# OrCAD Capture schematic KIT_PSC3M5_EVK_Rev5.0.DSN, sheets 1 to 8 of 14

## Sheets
1 13. ACCESORIES: title: PSOC CONTROL C3M5 EVALUATION KIT; rev: 5.0; note: 630-60703-01
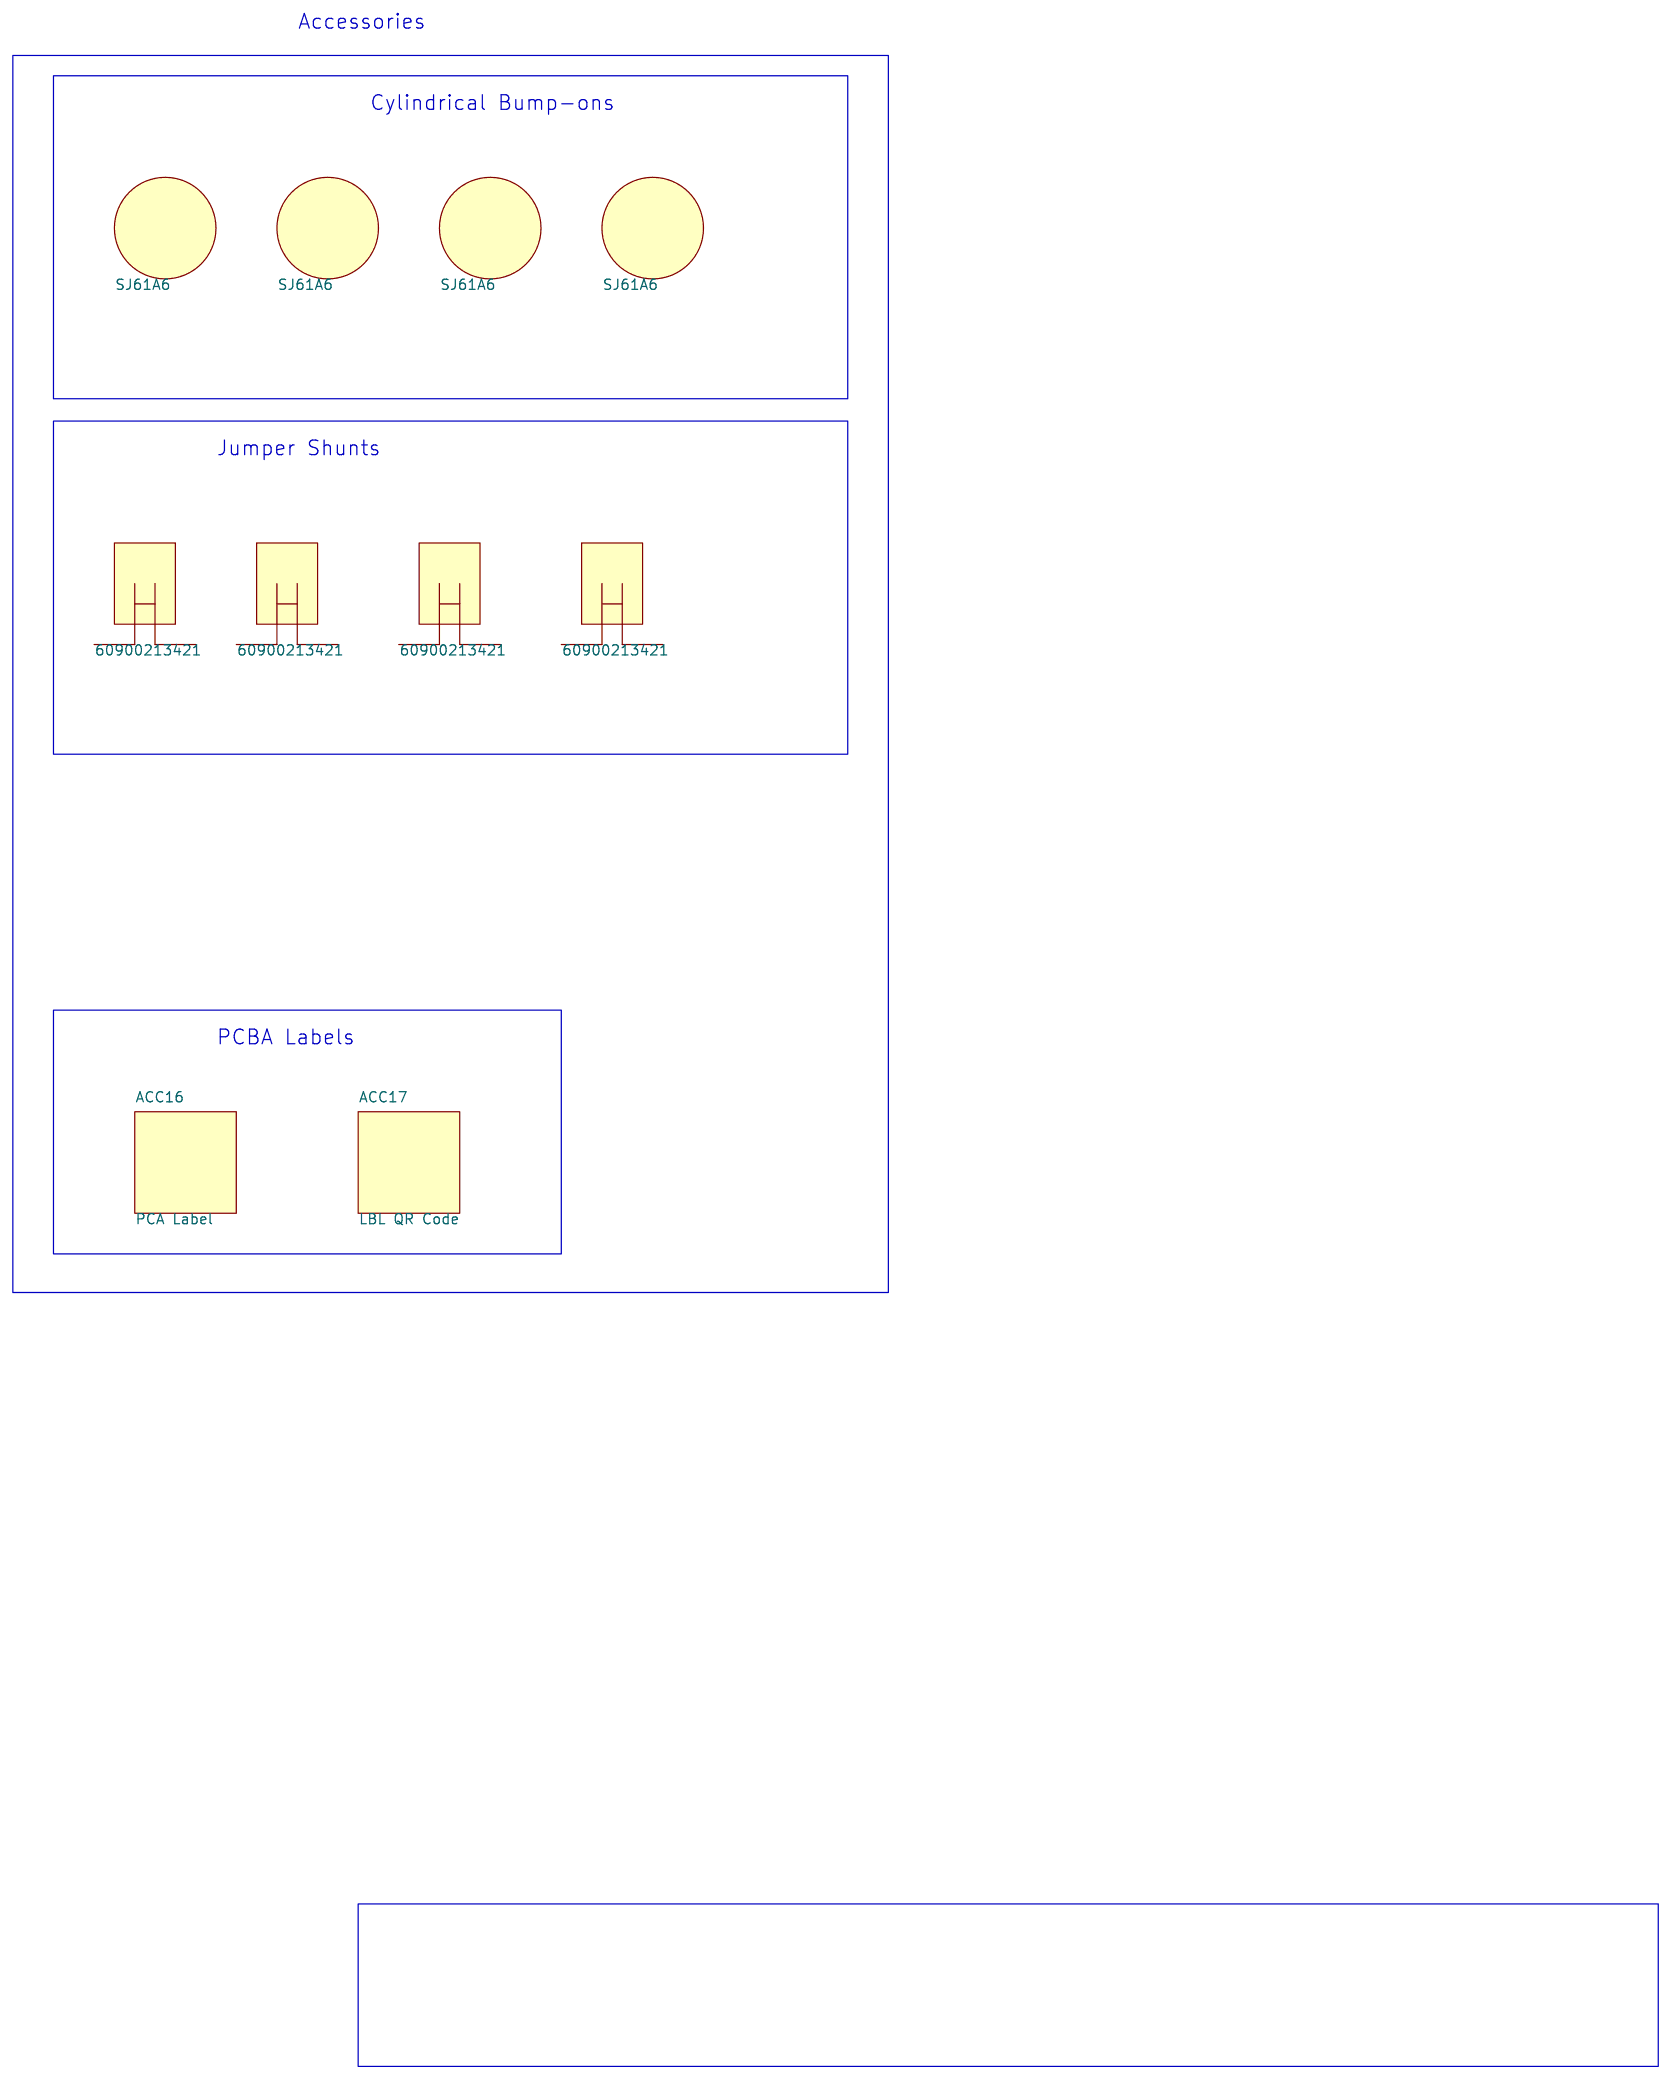
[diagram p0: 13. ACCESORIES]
2 01. TITLE PAGE
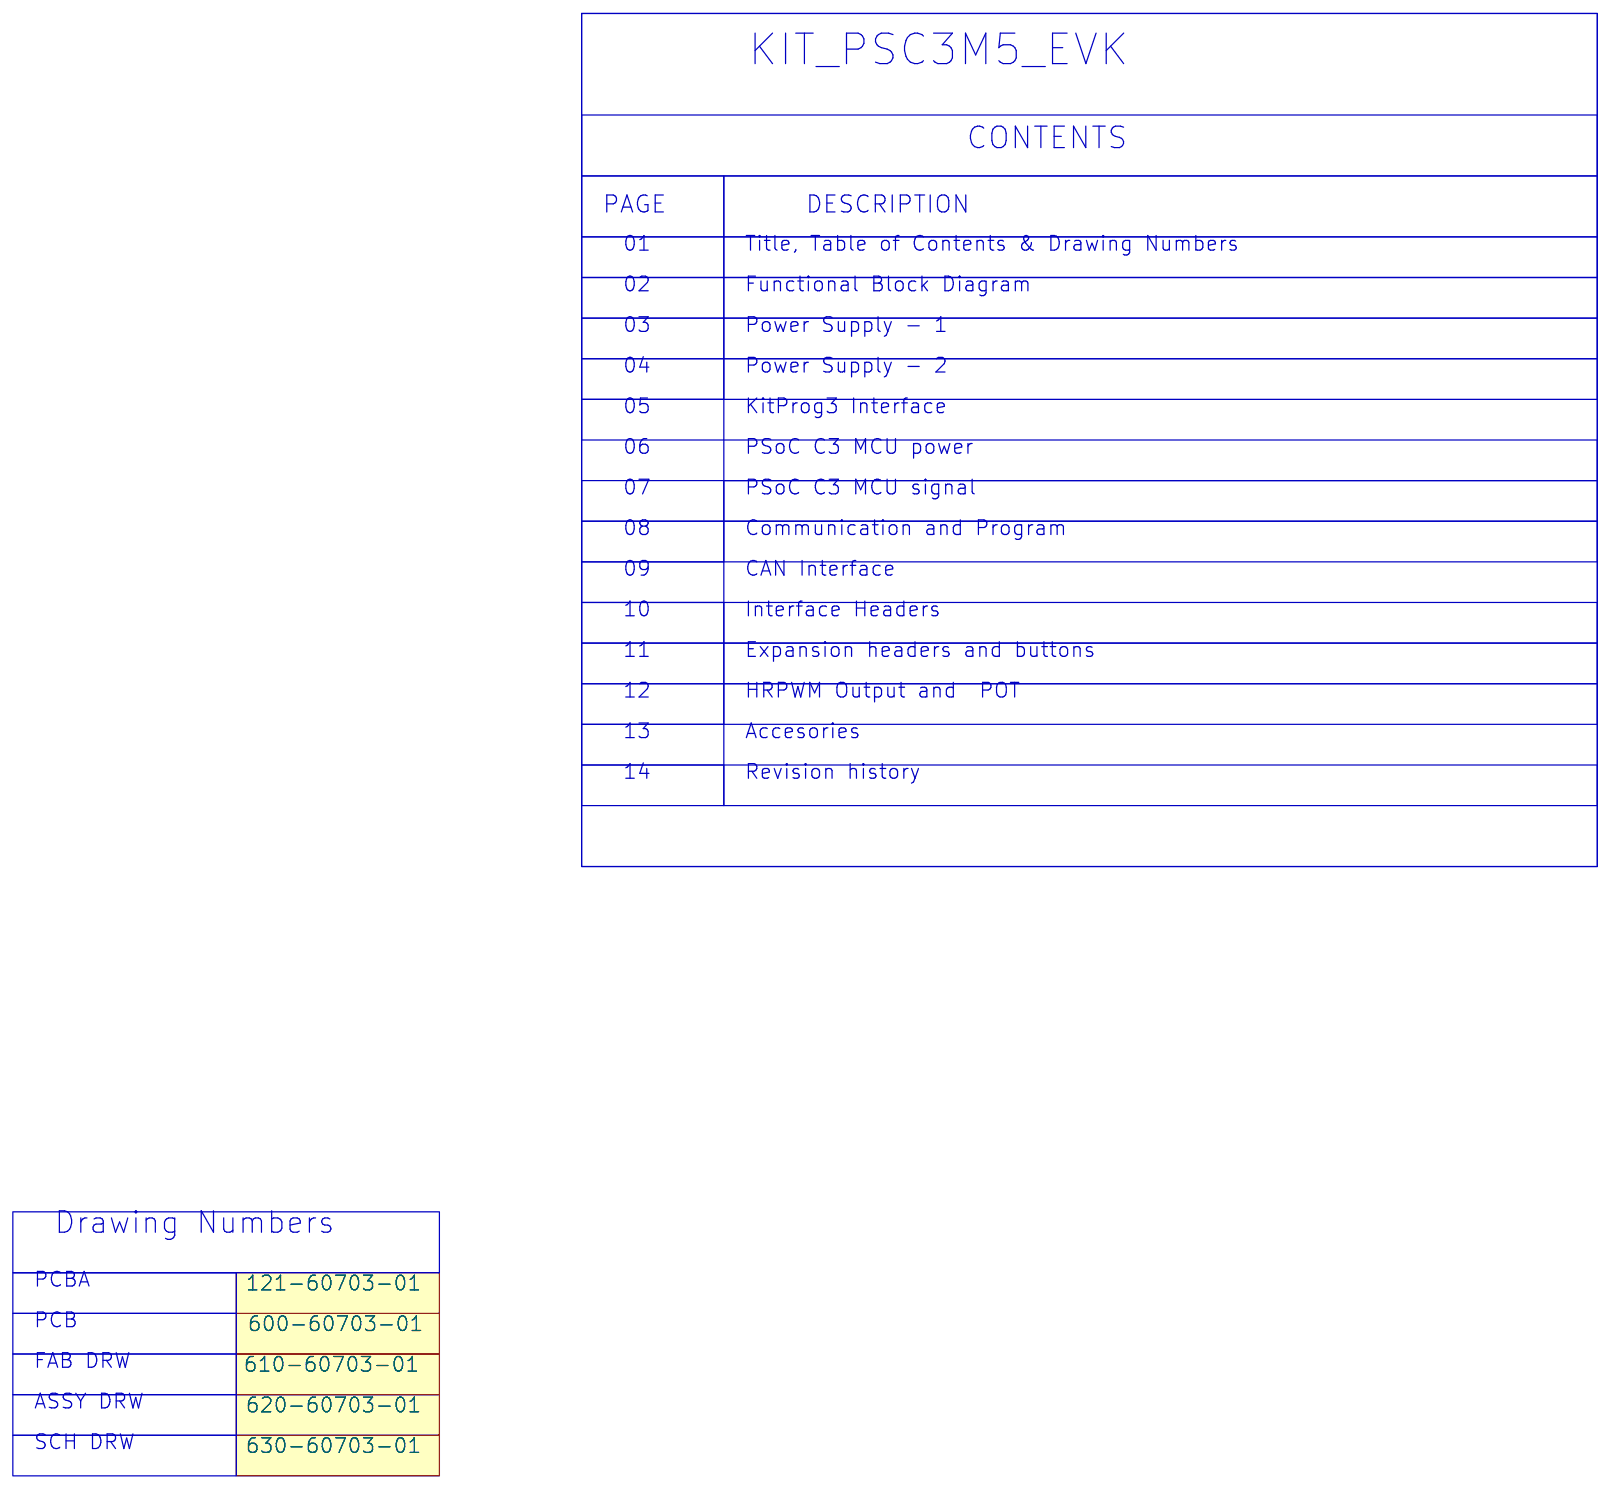
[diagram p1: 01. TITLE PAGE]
3 02. BLOCK DIAGRAM
4 03. POWER SUPPLY-1: size A4
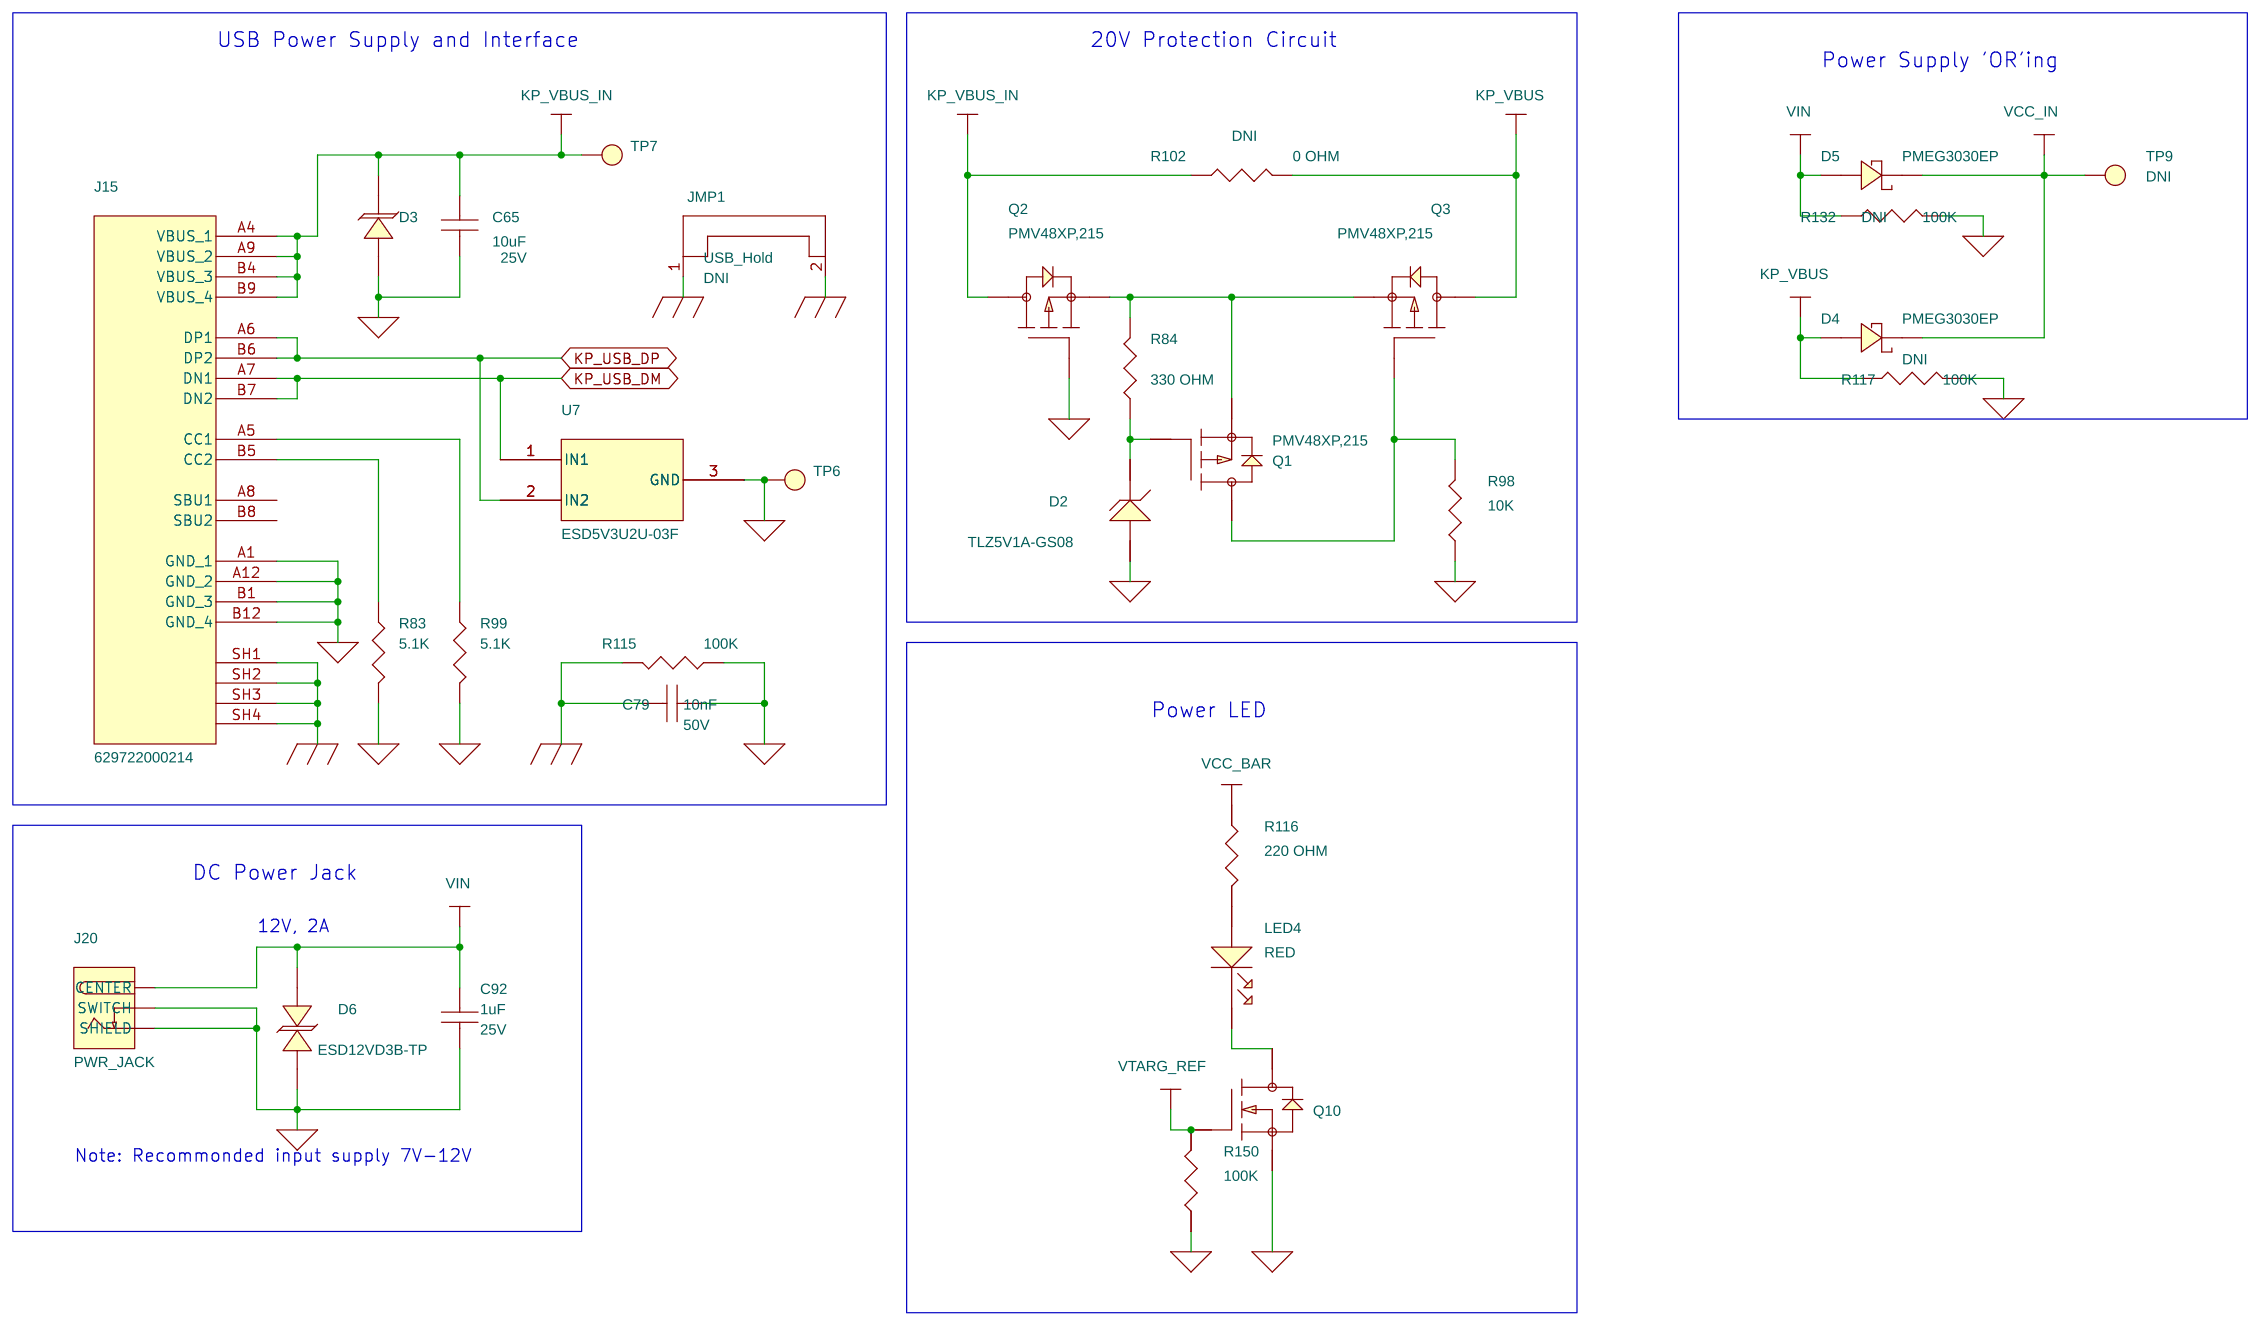
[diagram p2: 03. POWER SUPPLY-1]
5 04. POWER SUPPLY-2: size A4
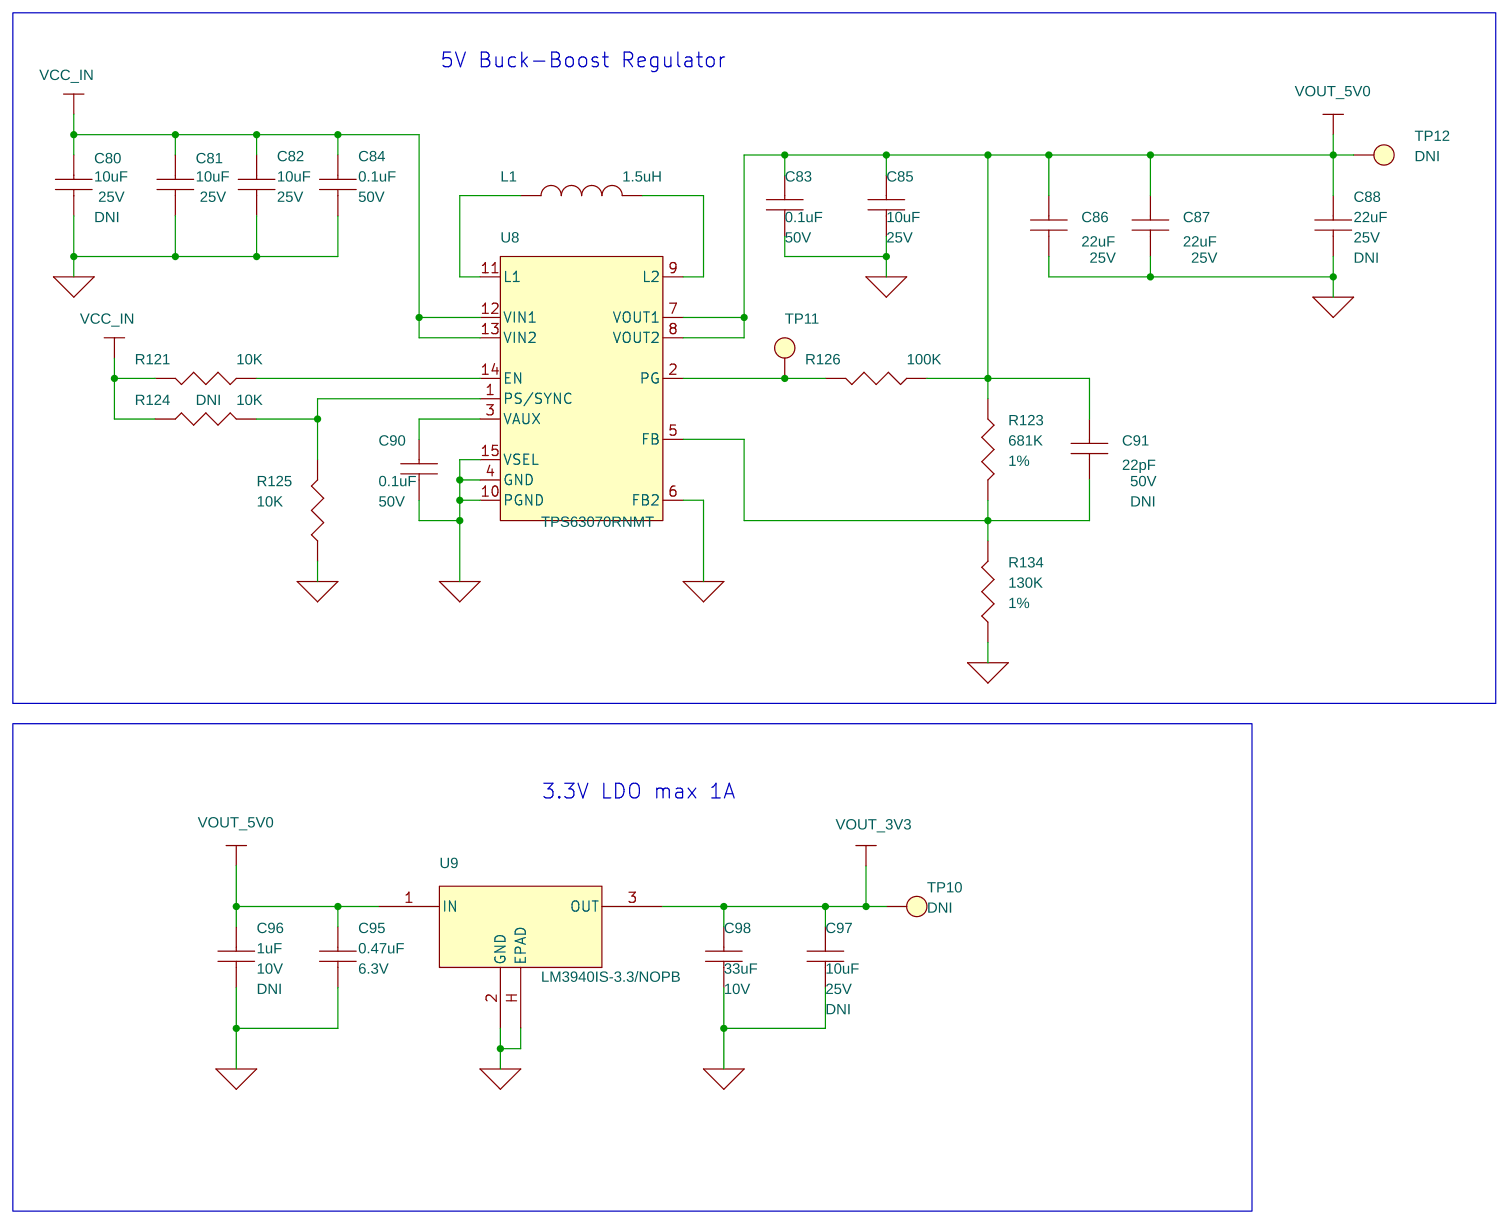
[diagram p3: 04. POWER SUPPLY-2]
6 05. KITPROG INTERFACE: size A4
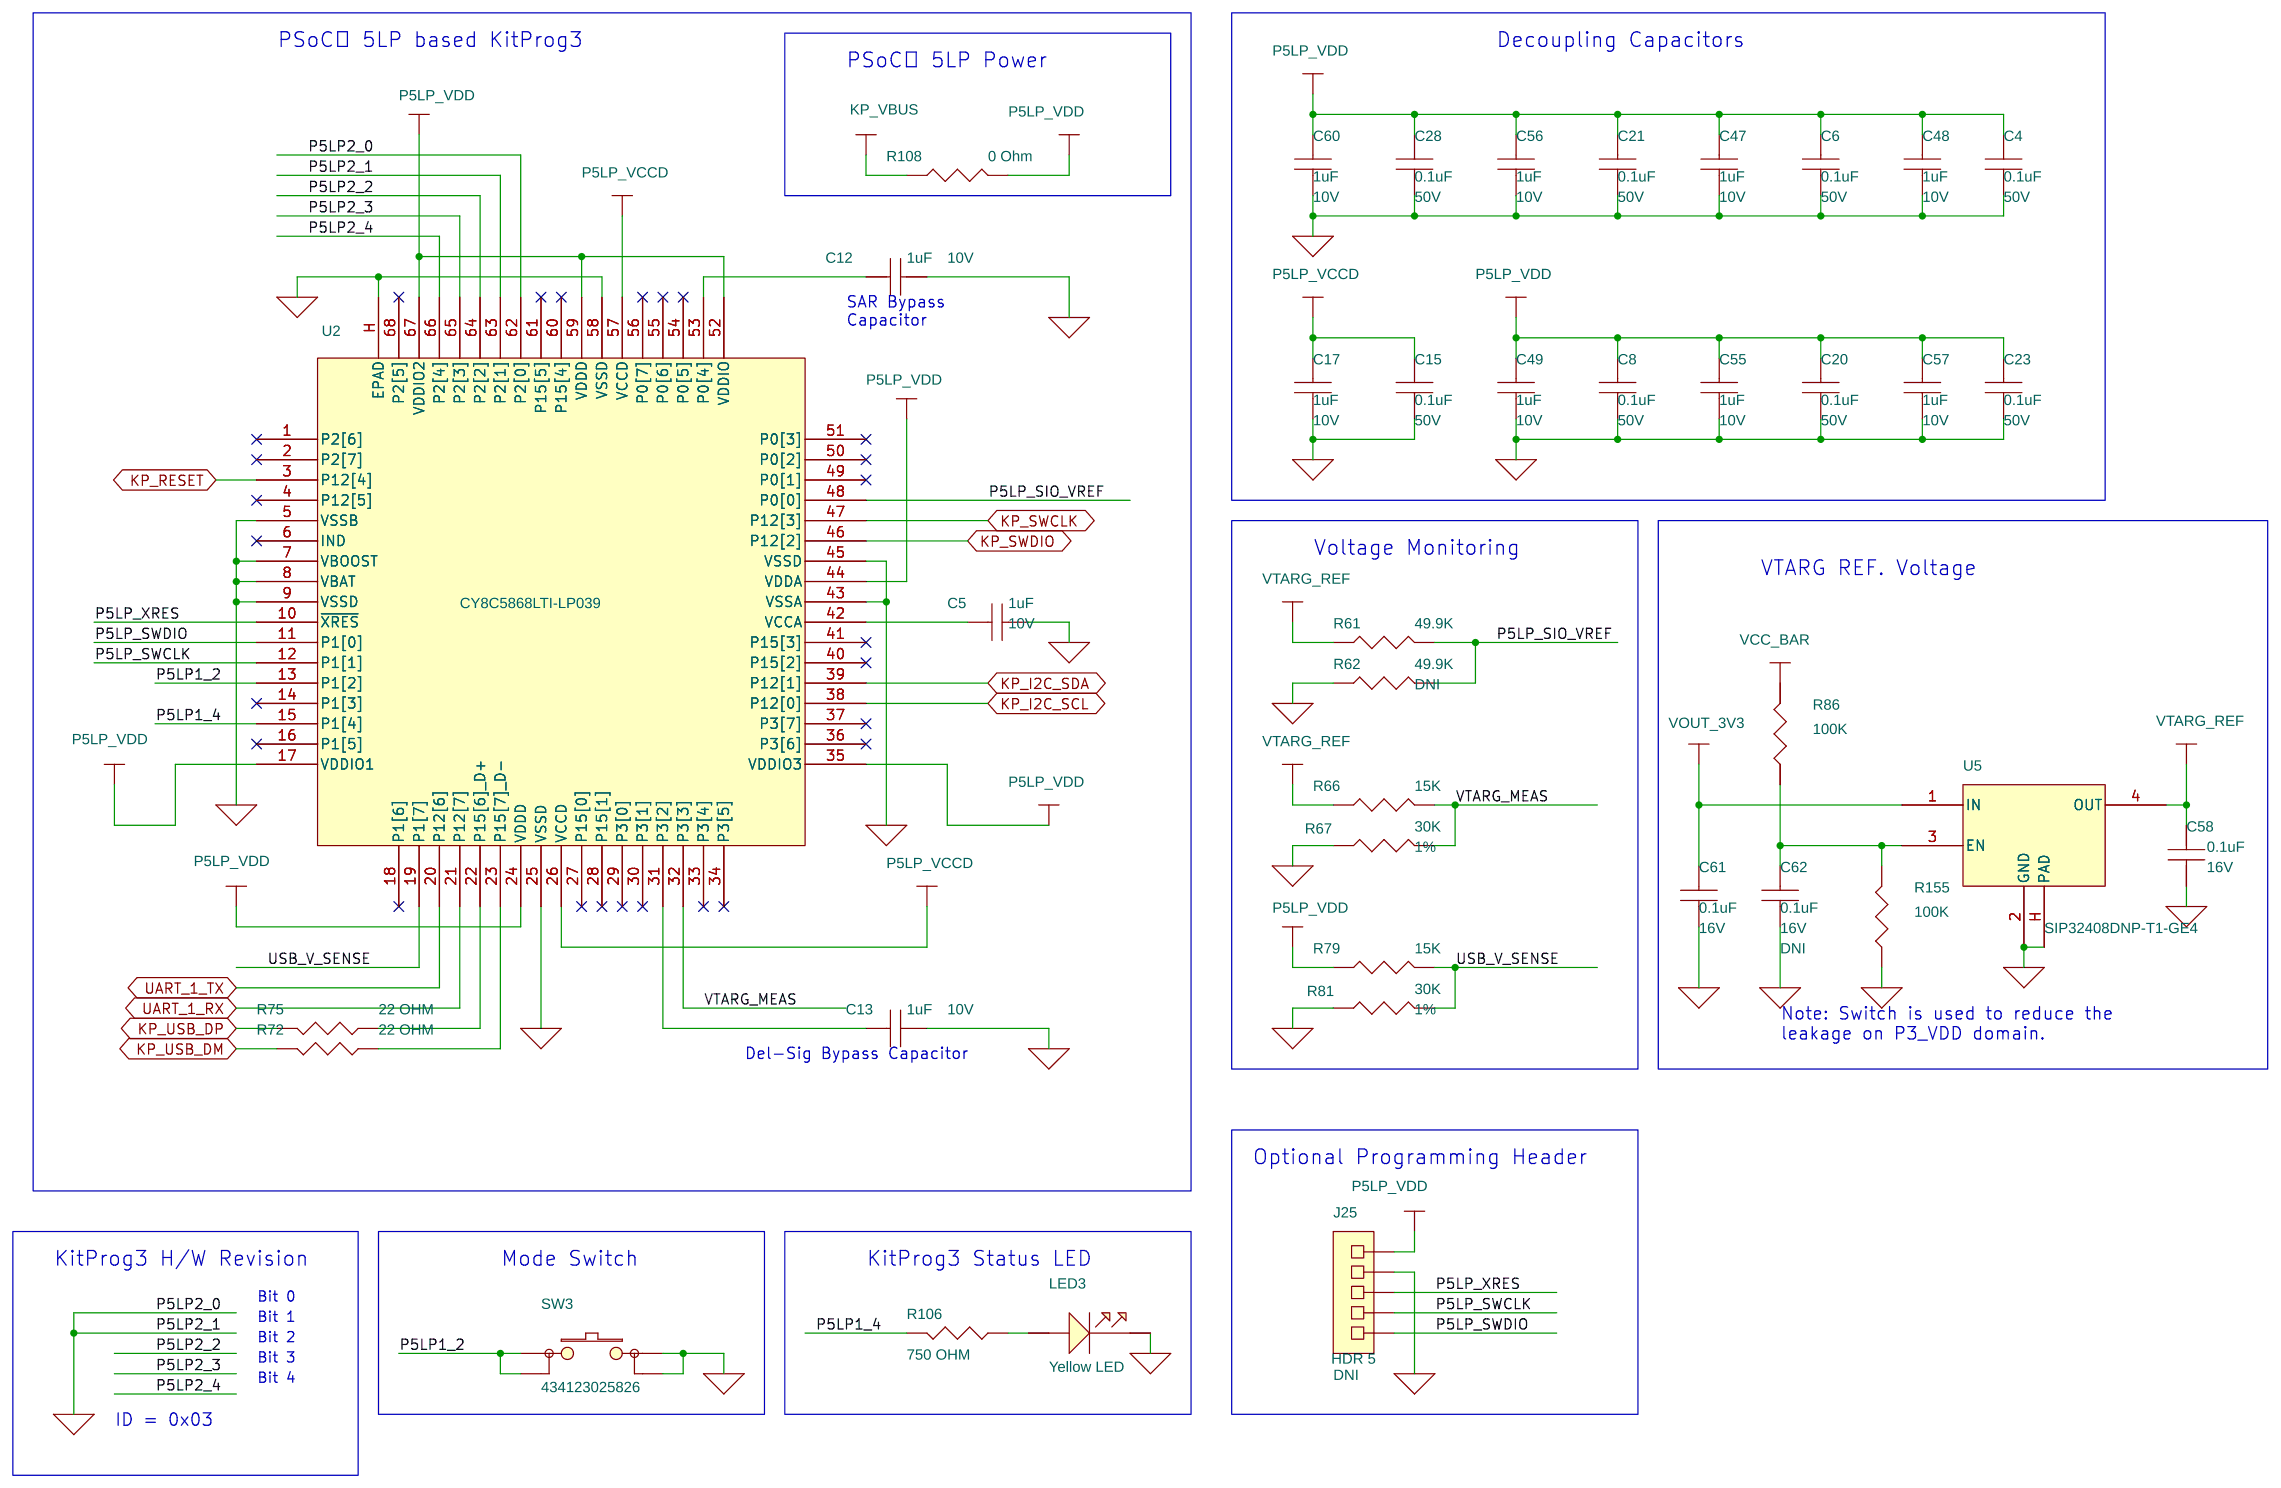
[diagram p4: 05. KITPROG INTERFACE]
7 06. PSOC C3 MCU POWER: size A4
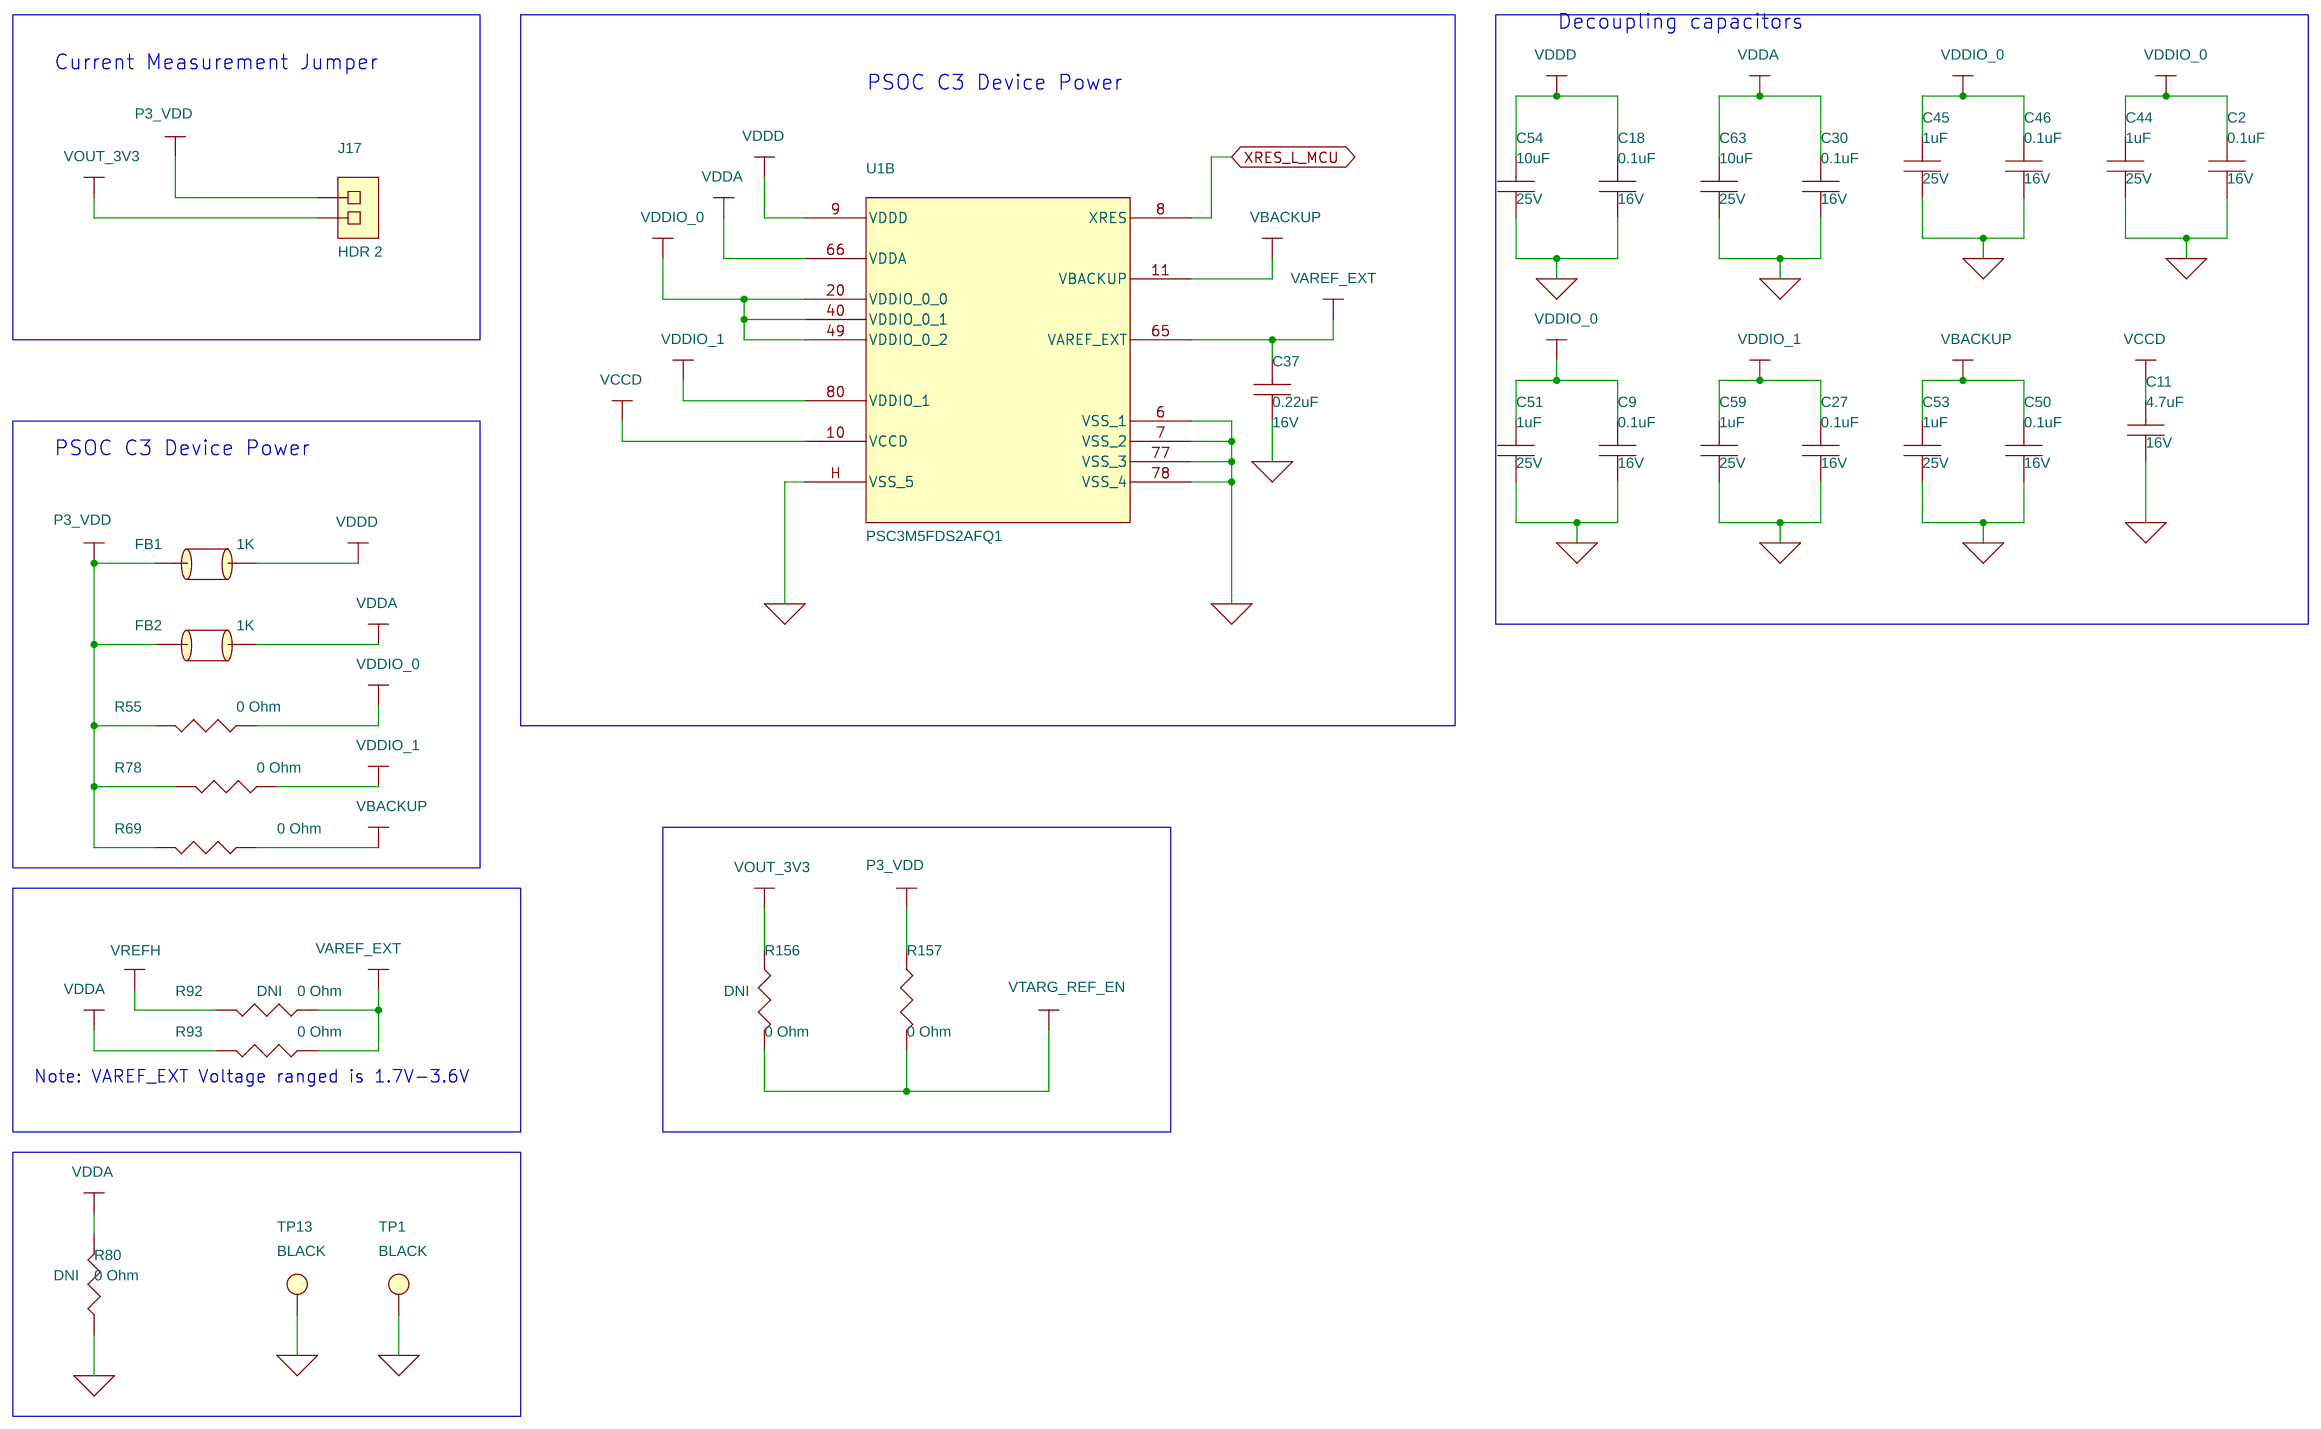
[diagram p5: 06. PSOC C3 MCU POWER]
8 07. PSOC C3 MCU SIGNAL: size A4
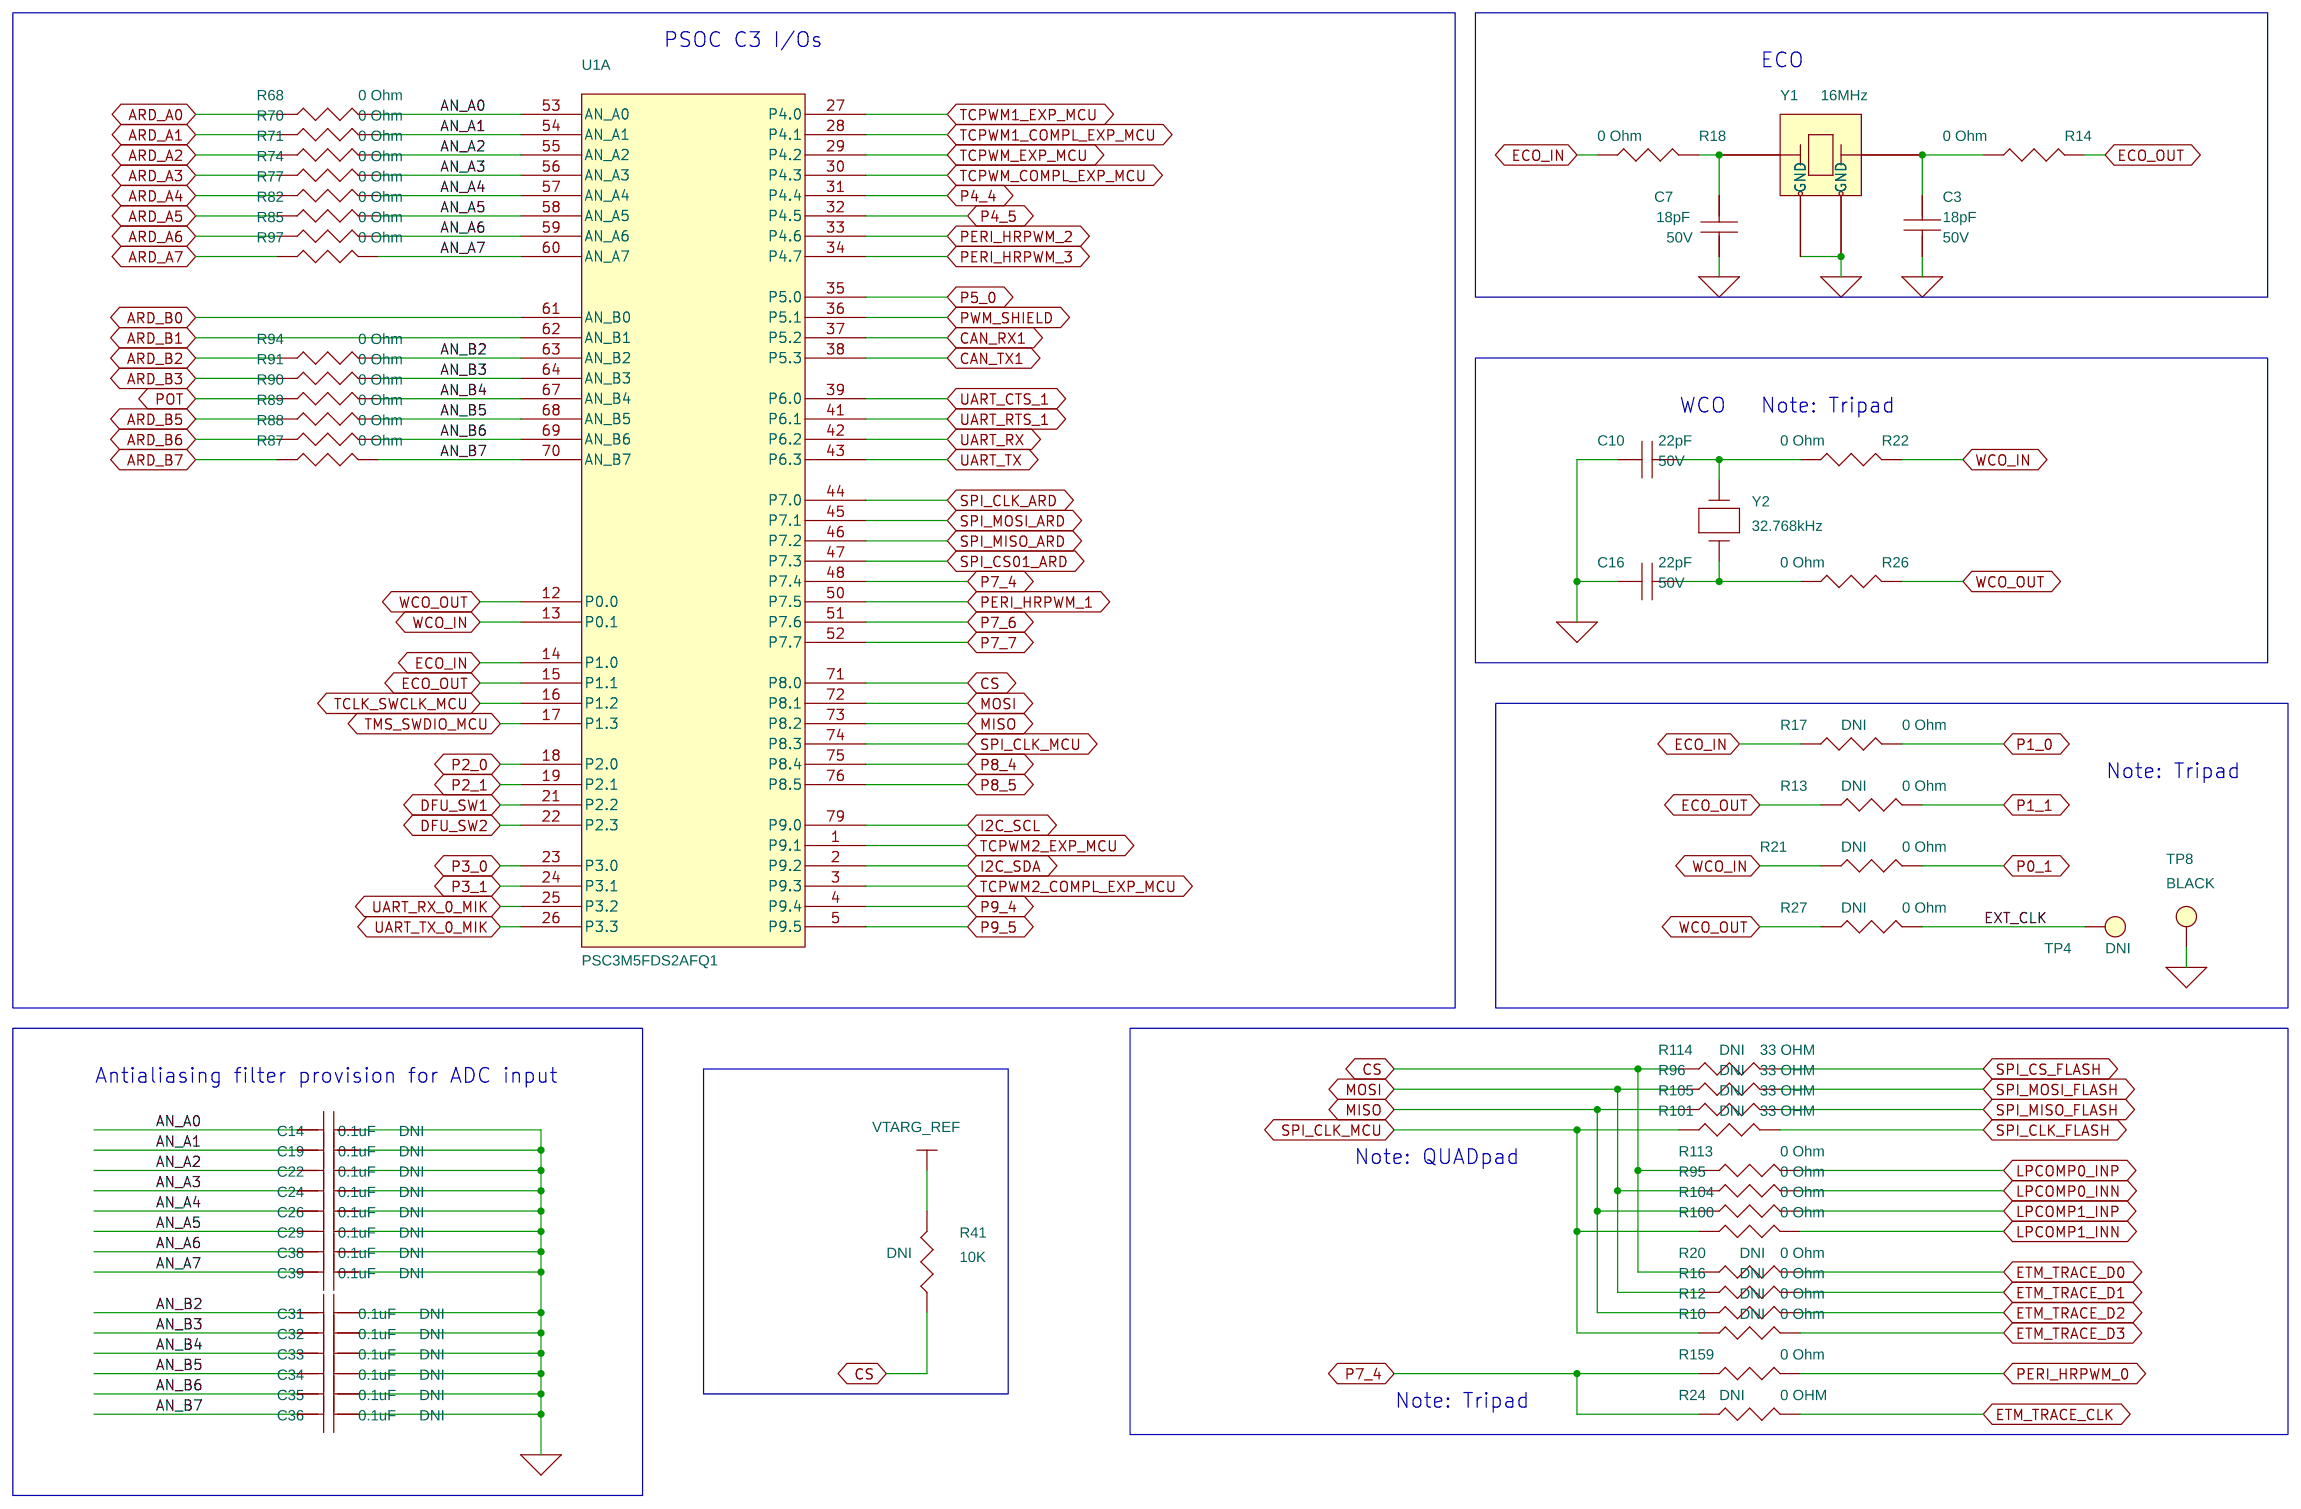
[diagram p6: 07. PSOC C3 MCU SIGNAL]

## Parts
sheet 01. TITLE PAGE
ACC1  121-60703-01  [TBD]
ACC2  600-60703-01  [TBD]
ACC3  610-60703-01  [TBD]
ACC4  620-60703-01  [TBD]
ACC5  630-60703-01  [TBD]
sheet 03. POWER SUPPLY-1
C65  10uF  [CAPC1608_0603N]
C79  10nF  [CAPC1005_0402N]
C92  1uF  [CAPC1608_0603N]
D2  TLZ5V1A-GS08  [DIOMELF3515N]
D3  SD05-7  [DIO2_SOD323N]
D4  PMEG3030EP  [DIO_NXP_SOD-128]
D5  PMEG3030EP  [DIO_NXP_SOD-128]
D6  ESD12VD3B-TP  [DIO2_SOD323_BIQ]
J15  629722000214  [GCT_USB4105-GF-A]
J20  PWR_JACK  [CUI_PJ-102A]
JMP1  USB_Hold  [CON_RA_STIFF_1000P]
LED4  RED  [LEDC2012_0805]
Q1  PMV48XP,215  [SOT95P230X110-3N]
Q2  PMV48XP,215  [SOT95P230X110-3N]
Q3  PMV48XP,215  [SOT95P230X110-3N]
Q10  NX3020NAKW,115  [SOT323_SC70-3N_NXP]
R83  5.1K  [RESC1005_0402N]
R84  330 OHM  [RESC1005_0402M]
R98  10K  [RESC1005_0402N]
R99  5.1K  [RESC1005_0402N]
R102  0 OHM  [RESC2012X60N]
R115  100K  [RESC1005_0402N]
R116  220 OHM  [RESC1005_0402M]
R117  100K  [RESC1005_0402N]
R132  100K  [RESC1005_0402N]
R150  100K  [RESC1005_0402N]
TP6  TP_SMD  [tp102c]
TP7  TP_SMD  [tp102c]
TP9  RED  [TPT_KEY_5000]
U7  ESD5V3U2U-03F  [SOTFL40P120X59-3N]
sheet 04. POWER SUPPLY-2
C80  10uF  [CAPC2012_0805N]
C81  10uF  [CAPC2012_0805N]
C82  10uF  [CAPC2012_0805N]
C83  0.1uF  [CAPC1005_0402N]
C84  0.1uF  [CAPC1005_0402N]
C85  10uF  [CAPC1608_0603N]
C86  22uF  [CAPC2012_0805N]
C87  22uF  [CAPC2012_0805N]
C88  22uF  [CAPC2012_0805N]
C90  0.1uF  [CAPC1005_0402N]
C91  22pF  [CAPC1005_0402N]
C95  0.47uF  [CAPC1005_0402N]
C96  1uF  [CAPC1005_0402N]
C97  10uF  [CAPC1608_0603N]
C98  33uF  [CAPC2012_0805N]
L1  1.5uH  [PULSE_PA4332]
R121  10K  [RESC1005_0402N]
R123  681K  [RESC1005_0402N]
R124  10K  [RESC1005_0402N]
R125  10K  [RESC1005_0402N]
R126  100K  [RESC1005_0402N]
R134  130K  [RESC1005_0402N]
TP10  RED  [TPT_KEY_5000]
TP11  TP_SMD  [tp102c]
TP12  RED  [TPT_KEY_5000]
U8  TPS63070RNMT  [qfn50p250x300x100-15m_NOFID]
U9  LM3940IS-3.3/NOPB  [TO254P1524X483-4N_TI]
sheet 05. KITPROG INTERFACE
C4  0.1uF  [CAPC1005_0402N]
C5  1uF  [CAPC1005_0402N]
C6  0.1uF  [CAPC1005_0402N]
C8  0.1uF  [CAPC1005_0402N]
C12  1uF  [CAPC1005_0402N]
C13  1uF  [CAPC1005_0402N]
C15  0.1uF  [CAPC1005_0402N]
C17  1uF  [CAPC1005_0402N]
C20  0.1uF  [CAPC1005_0402N]
C21  0.1uF  [CAPC1005_0402N]
C23  0.1uF  [CAPC1005_0402N]
C28  0.1uF  [CAPC1005_0402N]
C47  1uF  [CAPC1005_0402N]
C48  1uF  [CAPC1005_0402N]
C49  1uF  [CAPC1005_0402N]
C55  1uF  [CAPC1005_0402N]
C56  1uF  [CAPC1005_0402N]
C57  1uF  [CAPC1005_0402N]
C58  0.1uF  [CAPC1005_0402N]
C60  1uF  [CAPC1005_0402N]
C61  0.1uF  [CAPC1005_0402N]
C62  0.1uF  [CAPC1005_0402N]
J25  HDR 5  [CTST254P1X05_W260]
LED3  Yellow LED  [LEDC2012_0805]
R61  49.9K  [RESC1005_0402N]
R62  49.9K  [RESC1005_0402N]
R66  15K  [RESC1005_0402N]
R67  30K  [RESC1005_0402N]
R72  22 OHM  [RESC1005_0402N]
R75  22 OHM  [RESC1005_0402N]
R79  15K  [RESC1005_0402N]
R81  30K  [RESC1005_0402N]
R86  100K  [RESC1005_0402N]
R106  750 OHM  [RESC1005_0402M]
R108  0 Ohm  [RESC1608_0603N]
R155  100K  [RESC1005_0402N]
SW3  434123025826  [SW_SKRPACE010]
U2  CY8C5868LTI-LP039  [QFN40P800X800_68-H580N]
U5  SIP32408DNP-T1-GE4  [TDFN50P160X120_4-HS86X50M]
sheet 06. PSOC C3 MCU POWER
C2  0.1uF  [CAPC1005_0402N]
C9  0.1uF  [CAPC1005_0402N]
C11  4.7uF  [CAPC1608_0603N]
C18  0.1uF  [CAPC1005_0402N]
C27  0.1uF  [CAPC1005_0402N]
C30  0.1uF  [CAPC1005_0402N]
C37  0.22uF  [CAPC1005_0402N]
C44  1uF  [CAPC1608_0603N]
C45  1uF  [CAPC1608_0603N]
C46  0.1uF  [CAPC1005_0402N]
C50  0.1uF  [CAPC1005_0402N]
C51  1uF  [CAPC1608_0603N]
C53  1uF  [CAPC1608_0603N]
C54  10uF  [CAPC1608_0603N]
C59  1uF  [CAPC1608_0603N]
C63  10uF  [CAPC1608_0603N]
FB1  1K  [INDC1608_0603N]
FB2  1K  [INDC1608_0603N]
J17  HDR 2  [CTST254P1X02_W260]
R55  0 Ohm  [RESC1608_0603N]
R69  0 Ohm  [RESC1608_0603N]
R78  0 Ohm  [RESC1608_0603N]
R80  0 Ohm  [RESC1608_0603N]
R92  0 Ohm  [RESC1608_0603N]
R93  0 Ohm  [RESC1608_0603N]
R156  0 Ohm  [RESC1608_0603N]
R157  0 Ohm  [RESC1608_0603N]
TP1  BLACK  [TPT_KEY_5000]
TP13  BLACK  [TPT_KEY_5000]
sheet 07. PSOC C3 MCU SIGNAL
C3  18pF  [CAPC1005_0402N]
C7  18pF  [CAPC1005_0402N]
C10  22pF  [CAPC1005_0402N]
C14  0.1uF  [CAPC1608_0603N]
C16  22pF  [CAPC1005_0402N]
C19  0.1uF  [CAPC1608_0603N]
C22  0.1uF  [CAPC1608_0603N]
C24  0.1uF  [CAPC1608_0603N]
C26  0.1uF  [CAPC1608_0603N]
C29  0.1uF  [CAPC1608_0603N]
C31  0.1uF  [CAPC1608_0603N]
C32  0.1uF  [CAPC1608_0603N]
C33  0.1uF  [CAPC1608_0603N]
C34  0.1uF  [CAPC1608_0603N]
C35  0.1uF  [CAPC1608_0603N]
C36  0.1uF  [CAPC1608_0603N]
C38  0.1uF  [CAPC1608_0603N]
C39  0.1uF  [CAPC1608_0603N]
R10  0 Ohm  [RESC1608_0603N]
R12  0 Ohm  [RESC1608_0603N]
R13  0 Ohm  [RESC1608_0603N]
R14  0 Ohm  [RESC1608_0603N]
R16  0 Ohm  [RESC1608_0603N]
R17  0 Ohm  [RESC1608_0603N]
R18  0 Ohm  [RESC1608_0603N]
R20  0 Ohm  [RESC1608_0603N]
R21  0 Ohm  [RESC1608_0603N]
R22  0 Ohm  [RESC1608_0603N]
R24  0 OHM  [RESC1608_0603N]
R26  0 Ohm  [RESC1608_0603N]
R27  0 Ohm  [RESC1608_0603N]
R41  10K  [RESC1608_0603N]
R68  0 Ohm  [RESC1608_0603N]
R70  0 Ohm  [RESC1608_0603N]
R71  0 Ohm  [RESC1608_0603N]
R74  0 Ohm  [RESC1608_0603N]
R77  0 Ohm  [RESC1608_0603N]
R82  0 Ohm  [RESC1608_0603N]
R85  0 Ohm  [RESC1608_0603N]
R87  0 Ohm  [RESC1608_0603N]
R88  0 Ohm  [RESC1608_0603N]
R89  0 Ohm  [RESC1608_0603N]
R90  0 Ohm  [RESC1608_0603N]
R91  0 Ohm  [RESC1608_0603N]
R94  0 Ohm  [RESC1608_0603N]
R95  0 Ohm  [RESC1608_0603N]
R96  33 OHM  [RESC1608_0603N]
R97  0 Ohm  [RESC1608_0603N]
R100  0 Ohm  [RESC1608_0603N]
R101  33 OHM  [RESC1608_0603N]
R104  0 Ohm  [RESC1608_0603N]
R105  33 OHM  [RESC1608_0603N]
R113  0 Ohm  [RESC1608_0603N]
R114  33 OHM  [RESC1608_0603N]
R159  0 Ohm  [RESC1608_0603N]
TP4  RED  [TPT_KEY_5000]
TP8  BLACK  [TPT_KEY_5000]
U1  PSC3M5FDS2AFQ1  [LQFP50P1400X1400X160-81N]  (sections A,B)
Y1  16MHz  [OSCCC200X250X90-4M]
Y2  32.768kHz  [XTAL_ABS05_1M6X1M]
sheet 13. ACCESORIES
ACC6  SJ61A6  [3M_SJ61A6]
ACC7  SJ61A6  [3M_SJ61A6]
ACC8  SJ61A6  [3M_SJ61A6]
ACC9  SJ61A6  [3M_SJ61A6]
ACC11  60900213421  [TBD]
ACC12  60900213421  [TBD]
ACC13  60900213421  [TBD]
ACC16  PCA Label  [TBD]
ACC17  LBL QR Code  [TBD]
ACC18  60900213421  [TBD]

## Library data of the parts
ACC1 = PCB: ASSY, PCBA,PSOC CONTROL C3 EVALUATION KIT; Manufacturer: Cypress Approved CM; Manufacturer_PN: -NA-; Mfr_Name: Cypress Approved CM; Mfr_Part#: -NA-; Mfr_Part_Number: -NA-
ACC2 = PCB: PCB, BARE,PSOC CONTROL C3 EVALUATION KIT; Manufacturer: Cypress Approved CM; Manufacturer_PN: -NA-; Mfr_Name: Cypress Approved CM; Mfr_Part#: -NA-; Mfr_Part_Number: -NA-
ACC3 = PCB: DRW, FABRICATION DRAWING, PSOC CONTROL C3 EVALUATION KIT; Manufacturer: -NA-; Manufacturer_PN: -NA-; Mfr_Name: -NA-; Mfr_Part#: -NA-; Mfr_Part_Number: -NA-
ACC4 = PCB: DRW, ASSEMBLY DRAWING, PSOC CONTROL C3 EVALUATION KIT; Manufacturer: -NA-; Manufacturer_PN: -NA-; Mfr_Name: -NA-; Mfr_Part#: -NA-; Mfr_Part_Number: -NA-
ACC5 = PCB: DRW, SCHEMATIC DRAWING,PSOC CONTROL C3 EVALUATION KIT; Manufacturer: -NA-; Manufacturer_PN: -NA-; Mfr_Name: -NA-; Mfr_Part#: -NA-; Mfr_Part_Number: -NA-
C54 C63 C65 C85 = CAP-NP: CAP, CER, 10uF, 20%, X5R, 25V, 0603; Approved: Approved; CY_PN: 510-60180-01; Device_File: 510-60180-01; Dielectric: X5R; FPLIST: CAPC1608_0603N,CAPC1608_0603M; Lifecycle: Active; Manufacturer: Wurth; Manufacturer_PN: 885012106031; Operating_Temp: -55°C ~ 85°C; Package: 0603; Part_Status: In Prod; Tolerance: 20%; Voltage: 25V
C79 = CAP-NP: CAP, CER, 10nF, 10%, X7R, 50V, 0402; Approved: Approved; CY_PN: 510-60089-01; Device_File: 510-60089-01; Dielectric: X7R; FPLIST: CAPC1005_0402N,CAPC1005_0402M; Lifecycle: Active; Manufacturer: Wurth; Manufacturer_PN: 885012205067; Operating_Temp: -55°C ~ 125°C; Package: 0402; Part_Status: In Prod; Tolerance: 10%; Voltage: 50V
C44 C45 C51 C53 C59 C92 = CAP-NP: CAP, CER, 1uF, 10%, X7R, 25V, 0603; CY_PN: 510-60064-01; Device File: 510-60064-01; Device_File: 510-60064-01; Dielectric: X7R; FPLIST: CAPC1608_0603N,CAPC1608_0603M; Lifecycle: Active; Manufacturer: Wurth; Manufacturer_PN: 885012206076; Operating_Temp: -55°C to 125°C; Package: 0603; Part Status: In Prod; Part_Status: In Prod; Tolerance: 10%; Voltage: 25V
D2 = DIO-ZENER: DIO, ZENER, 5.1V, 0.5W, SOD-80; CY_PN: 530-60166-01; Device_File: 530-60166-01; Lifecycle: Active; Manufacturer: Vishay; Operating_Temp: -40°C to 85°C; Package: SOD-80; Part_Status: In Des; Rating: 0.5W; Voltage: 5.1V
D3 = DIO-TVS: DIO, TVS, UNIDIR, 5V, 14.5V, 350W, SOD-323; CY_PN: 530-60056-01; Device_File: 530-60056-01; Lifecycle: Active; Manufacturer: Diodes Inc; Operating_Temp: -55°C to 150°C; Package: SOD-323; Part_Status: In Prod; Rating: 350W; Voltage: 5V
D4 D5 = DIO-SCHOTTKY: DIO, SCHOTTKY, 30V, 3A, SOD128, SURFACE MOUNT; CY_PN: 530-60216-01; FPLIST: DIO2_NXP_SOD128M,DIO2_NXP_SOD128N; Manufacturer: NXP; Manufacturer_PN: PMEG3030EP,115; Operating Temp: -55°C to 150°C; Part Type: SCHOTTKY
D6 = DIO-TVS-BI: DIO, TVS, BIDIR, 12VRWM, 15.5VC, 350W, SOD-323; CY_PN: 530-60192-01; Device_File: 530-60192-01; Lifecycle: Active; Manufacturer: MCC; Operating_Temp: -55°C to 150°C; Package: SOD-323; Part_Status: In Des; Rating: 350W; Voltage: 12V
J15 = USB_TYPE_C-16PIN_4SH: CONN, RCPT, USB, TYPE-C, USB2.0, 12POS, TOP MOUNT, RA, SMD; Approved: Approved; CY_PN: 720-60675-01; Conatct_Length: NA; Contact_Finish: GOLD; Current_Rating: 5A; Device_File: 720-60675-01; Lifecycle: Active; Manufacturer: Wurth; Mated_Height: NA; Operating_Temp: -40°C to +85°C; Part_Status: In Prod; Pin_Pitch: NA; Pins: 12; Row_pitch: NA; Rows: 1; Shrouding: NA
J20 = JACK-PWR-3P: CONN, DC PWR JACK, MALE, UnShielded, 2.5A, 2.1mm Inner Dia, 5.5mm Outer Dia, RA, TH; Approved: Approved; CY_PN: 720-60005-01; Conatct_Length: NA; Contact_Finish: TIN; Current_Rating: 2.5A; Description1: 24V max, 5000 Cylces, Single Switch Normally Closed; Device_File: 720-60005-01; Lifecycle: Active; Manufacturer: CUI Devices; Manufacturer_PN: PJ-102A; Mated_Height: NA; Operating_Temp: -25°C to 85°C; Part_Status: In Prod; Pin_Pitch: NA; Pins: 3; Row_pitch: NA; Rows: NA; Shrouding: NA
JMP1 = USB_HOLD: WIRE, WIRE BUS BAR 1000' LONG, THICKNESS 22 AWG; BOM_Notes: Each quantity to be considered as wire segment of 28mm; CY_PN: 751-60031-01; Conatct_Length: NA; Contact_Finish: NA; Current_Rating: NA; DNI: DNI; Description1: USB Type-C Connector Holding Wire, 13mm pitch Footprint; Device_File: 751-60031-01; Manufacturer: Alpha Wire; Manufacturer_PN: 298SV001; Mated_Height: NA; Operating_Temp: NA; Part_Status: In Prod; Row_pitch: NA; Shrouding: NA
LED4 = DIO-LED: LED, Red, Clear, 640nm, 2.0V, 0805; Approved: Approved; CY_PN: 534-60064-01; Device_File: 534-60064-01; Lifecycle: Active; Manufacturer: VCC; Manufacturer_PN: CMD17-21VRC/TR8; Operating_Temp: -40°C ~ 85°C; Package: 0805; Part_Status: In Prod; Rating: NA; Voltage: 2.0V
Q1-Q3 = FET-MOS-P: FET, MOSFET, P-CH, 20V, 3.5A, 0.51W, SOT-23; CY_PN: 532-60017-01; Current: 3.5A; Device_File: 532-60017-01; FPLIST: SOT95P230X110-3N,SOT23_G_S_D-NXP; Lifecycle: Active; Manufacturer: NXP; Operating_Temp: -55°C to 150°C; Package: SOT-23; Part_Status: In Prod; Power: 0.51W; Voltage: 20V
Q10 = FET-MOS-N: FET, MOSFET, N-CH, 30V, 0.18A, 0.26W, SOT-323; CY_PN: 532-60063-01; Costing: MCU and Power; Current: 0.18A; Device File: 532-60063-01; Device_File: 532-60063-01; Lifecycle: Active; Manufacturer: NXP; Operating_Temp: -55°C to 150°C; Package: SOT-323; Part_Status: In Des; Power: 0.26W; Voltage: 30V
R83 R99 = RES: RES, Fixed, 5.1K, 5%, 1/16W, 0402; CY_PN: 500-61022-01; Device_File: 500-61022-01; FPLIST: RESC1005_0402N,RESC1005_0402M; Lifecycle: Active; Manufacturer: Yageo; Manufacturer_PN: RC0402JR-075K1L; Operating_Temp: -55°C to 155°C; Package: 0402; Part_Status: In Production; Rating: 1/16W; Tolerance: 5%
R84 = RES: RES, Fixed, 330 OHM, 5%, 1/10W, 0402; Approved: Approved; CY_PN: 500-60306-01; Device_File: 500-60306-01; FPLIST: RESC1005_0402N,RESC1005_0402M; Lifecycle: Active; Manufacturer: Panasonic; Manufacturer_PN: ERJ-2GEJ331X; Operating_Temp: -55°C ~ 155°C; Package: 0402; Part_Status: In Prod; Rating: 1/10W; Tolerance: 5%
R98 R121 R125 = RES: RES, FIXED, 10K OHM, 5%, 1/10W, 0402; Approved: Approved; CY_PN: 500-60470-01; Device_File: 500-60470-01; FPLIST: RESC1005_0402N,RESC1005_0402M; Lifecycle: Active; Manufacturer: Wurth; Manufacturer_PN: 560112110006; Operating_Temp: -55°C ~ 155°C; Package: 0402; Part_Status: In Prod; Rating: 1/10W; Tolerance: 5%
R102 = RES: RES, 0 OHM, 5%, 1/8W, 0805; CY_PN: 500-61085-01; DNI: DNI; Device_File: 500-61085-01; Lifecycle: Active; Manufacturer: Yageo; Manufacturer_PN: AC0805JR-070RL; Operating_Temp: -55°C to 155°C; Package: 0402; Part_Status: Unrel; Rating: 1/8W
R86 R115 R150 R155 = RES: RES, FIXED, 100K OHM, 5%, 100PPM, 1/10W, 0402; Approved: Approved; CY_PN: 500-61389-01; Device_File: 500-61389-01; FPLIST: RESC1005_0402N,RESC1005_0402M; Lifecycle: Active; Manufacturer: Wurth; Manufacturer_PN: 560112110063; Operating_Temp: -55°C ~ 155°C; Package: 0402; Part_Status: unrel; Rating: 1/10W; Tolerance: 5%
R116 = RES: RES, FIXED, 220 OHM, 5%, 1/10W, 0402; Approved: Approved; CY_PN: 500-60993-01; Device_File: 500-60993-01; FPLIST: RESC1005_0402N,RESC1005_0402M; Lifecycle: Active; Manufacturer: Wurth; Manufacturer_PN: 560112110036; Operating_Temp: -55°C ~ 155°C; Package: 0402; Part_Status: In Prod; Rating: 1/10W; Tolerance: 5%
R117 R132 = RES: RES, FIXED, 100K OHM, 5%, 100PPM, 1/10W, 0402; Approved: Approved; CY_PN: 500-61389-01; DNI: DNI; Device_File: 500-61389-01; FPLIST: RESC1005_0402N,RESC1005_0402M; Lifecycle: Active; Manufacturer: Wurth; Manufacturer_PN: 560112110063; Operating_Temp: -55°C ~ 155°C; Package: 0402; Part_Status: unrel; Rating: 1/10W; Tolerance: 5%
TP6 TP7 TP11 = TP_SMD: TestPoint, PCB, Circle, 1mm, SMD; CY_PN: NA; DNI: DNI; Lifecycle: NA; Manufacturer: NA; Manufacturer_PN: NA; Part_Status: NA
TP9 TP12 = TP: TESTPOINT, PC, Mini, 0.040"D, Red, TH; CY_PN: 711-60001-01; Conatct_Length: NA; Contact_Finish: SILVER; Current_Rating: TBD; DNI: DNI; Device File: 711-60001-01; Device_File: 711-60001-01; Manufacturer: Keystone; Manufacturer_PN: 5000; Mated_Height: 4.57mm; Operating_Temp: TBD; Part_Status: In Des; Pins: 1; Row_pitch: NA; Shrouding: NA
U7 = ESD5V3U2U-03F: DIO, INFINEON, ESD Protection, 5.3V, 2CH, +/-20KV, SOT-723; Approved: Approved; Lifecycle: Active; Manufacturer: IFX; Operating_Temp: -40°C to 125°C; Package: SOT-723; Part_Status: Unrel; Rating: +/-20KV, 3A; Voltage: 5.3V
C80 = CAP-NP: CAP, CER, 10uF, 10%, X5R, 25V, 0805; CY_PN: 510-60052-01; DNI: DNI; Device File: 510-60052-01; Device_File: 510-60052-01; Dielectric: X5R; FPLIST: CAPC2012_0805N,CAPC2012_0805M; Manufacturer: Murata; Manufacturer_PN: GRM21BR61E106KA73L; Part Status: In Des; Tolerance: 10%; Voltage: 25V
C81 C82 = CAP-NP: CAP, CER, 10uF, 10%, X5R, 25V, 0805; CY_PN: 510-60052-01; Device File: 510-60052-01; Device_File: 510-60052-01; Dielectric: X5R; FPLIST: CAPC2012_0805N,CAPC2012_0805M; Manufacturer: Murata; Manufacturer_PN: GRM21BR61E106KA73L; Part Status: In Des; Tolerance: 10%; Voltage: 25V
C4 C6 C8 C15 C20 C21 C23 C28 C83 C84 C90 = CAP-NP: CAP, CER, 0.1uF, 10%, X7R, 50V, 0402; Approved: Approved; CY_PN: 510-60335-01; Device_File: 510-60335-01; Dielectric: X7R; FPLIST: CAPC1005_0402N,CAPC1005_0402M; Lifecycle: Active; Manufacturer: Wurth; Manufacturer_PN: 885012205086; Operating_Temp: -55°C ~ 125°C; Package: 0402; Part_Status: Unrel; Tolerance: 10%; Voltage: 50V
C86 C87 = CAP-NP: CAP, CER, 22uF, 20%, X5R, 25V, 0805; CY_PN: 510-60564-01; Device_File: 510-60564-01; Dielectric: X5R; FPLIST: CAPC2012_0805N,CAPC2012_0805M; Lifecycle: Active; Manufacturer: Murata; Manufacturer_PN: GRM21BR61E226ME44L; Operating_Temp: -55°C to 85°C; Package: 0805; Part_Status: In Des; Tolerance: 20%; Voltage: 25V
C88 = CAP-NP: CAP, CER, 22uF, 20%, X5R, 25V, 0805; CY_PN: 510-60564-01; DNI: DNI; Device File: 510-60564-01; Device_File: 510-60564-01; Dielectric: X5R; FPLIST: CAPC2012_0805N,CAPC2012_0805M; Lifecycle: Active; Manufacturer: Yageo; Manufacturer_PN: CC0805MKX5R8BB226; Operating_Temp: -55°C to 85°C; Package: 0805; Part_Status: In Des; Tolerance: 20%; Voltage: 25V
C91 = CAP-NP: CAP, CER, 22pF, 5%, NP0, 50V, 0402; Approved: Approved; CY_PN: 510-60716-01; DNI: DNI; Device_File: 510-60716-01; Dielectric: NP0; FPLIST: CAPC1005_0402N,CAPC1005_0402M; Lifecycle: Active; Manufacturer: Wurth; Manufacturer_PN: 885012005057; Operating_Temp: -55°C ~ 125°C; Package: 0402; Part_Status: In Prod; Tolerance: 5%; Voltage: 50V
C95 = CAP-NP: CAP, CER, 0.47uF, 20%, X5R, 6.3V, 0402; Approved: Approved; CY_PN: 510-61137-01; Device_File: 510-61137-01; Dielectric: X5R; FPLIST: CAPC1005_0402N,CAPC1005_0402M; Lifecycle: Active; Manufacturer: Wurth; Manufacturer_PN: 885012105004; Operating_Temp: -55°C ~ 85°C; Package: 0402; Part_Status: In Prod; Tolerance: 20%; Voltage: 6.3V
C96 = CAP-NP: CAP, CER, 1uF, 20%, 10V, X5R, 0402; Approved: Approved; CY_PN: 510-60877-01; DNI: DNI; Device_File: 510-60877-01; Dielectric: X5R; FPLIST: CAPC1005_0402N,CAPC1005_0402M; Lifecycle: Active; Manufacturer: Wurth; Manufacturer_PN: 885012105012; Operating_Temp: -55°C ~ 85°C; Package: 0402; Part_Status: In Prod; Tolerance: 20%; Voltage: 10V
C97 = CAP-NP: CAP, CER, 10uF, 20%, X5R, 25V, 0603; Approved: Approved; CY_PN: 510-60180-01; DNI: DNI; Device_File: 510-60180-01; Dielectric: X5R; FPLIST: CAPC1608_0603N,CAPC1608_0603M; Lifecycle: Active; Manufacturer: Wurth; Manufacturer_PN: 885012106031; Operating_Temp: -55°C ~ 85°C; Package: 0603; Part_Status: In Prod; Tolerance: 20%; Voltage: 25V
C98 = CAP-NP: CAP, CER, 33uF, 20%, X5R, 10V, 0805; Approved: Approved; CY_PN: 510-60370-01; Device_File: 510-60370-01; Dielectric: X5R; FPLIST: CAPC2012_0805N,CAPC2012_0805M; Lifecycle: Active; Manufacturer: TDK Electronics; Manufacturer_PN: C2012X5R1A336M125AC; Operating_Temp: -55°C ~ 85°C; Package: 0805; Part_Status: Unrel; Tolerance: 20%; Voltage: 10V
L1 = IND: IND, FIXED, SHIELDED, 1.5uH, 5.2A, 0.036 OHM, SMD; CY_PN: 520-60097-01; Current: 5.2A; DB_Status: Unverified; Device_File: 520-60097-01; ESR: 0.036 OHM; Lifecycle: Active; Manufacturer: PULSE; Manufacturer_PN: PA4332.152NLT; Material: WireWound; Operating_Temp: -40°C to 125°C; Package: SMD; Part_Status: In Des; Part_Type: Inductor; Tolerance: 20%
R123 = RES: RES, 681K OHM, 1%, 1/16W, 0402; CY_PN: 500-61084-01; FPLIST: RESC1005_0402N,RESC1005_0402M; Lifecycle: Active; Manufacturer: Yageo; Manufacturer_PN: AC0402FR-07681KL; Operating_Temp: -55°C to 155°C; Package: 0402; Part_Status: In Des; Rating: 1/16W; Tolerance: 1%
R124 = RES: RES, FIXED, 10K OHM, 5%, 1/10W, 0402; Approved: Approved; CY_PN: 500-60470-01; DNI: DNI; Device_File: 500-60470-01; FPLIST: RESC1005_0402N,RESC1005_0402M; Lifecycle: Active; Manufacturer: Wurth; Manufacturer_PN: 560112110006; Operating_Temp: -55°C ~ 155°C; Package: 0402; Part_Status: In Prod; Rating: 1/10W; Tolerance: 5%
R126 = RES: RES, FIXED, 100K OHM, 1%, 1/10W, 0402; Approved: Approved; CY_PN: 500-60338-01; Device_File: 500-60338-01; FPLIST: RESC1005_0402N,RESC1005_0402M; Lifecycle: Active; Manufacturer: Wurth; Manufacturer_PN: 560112110019; Operating_Temp: -55°C ~ 155°C; Package: 0402; Part_Status: In Prod; Rating: 1/10W; Tolerance: 1%
R134 = RES: RES, 130K OHM, 1%, 100PPM, 1/16W, 0402, SMD; CY_PN: 500-60888-01; Device File: 500-60888-01; Device_File: 500-60888-01; FPLIST: RESC1005_0402N,RESC1005_0402M; Lifecycle: Active; Manufacturer: Panasonic; Manufacturer_PN: ERJ-2RKF1303X; Operating_Temp: -55°C to 155°C; Package: 0402; Part_Status: In Prod; Rating: 1/16W; Tolerance: 1%; Wattage: 1/16W
TP4 TP10 = TP: TESTPOINT, PC, Mini, 0.040"D, Red, TH; CY_PN: 711-60001-01; Conatct_Length: NA; Contact_Finish: SILVER; Costing: 3V3 PS; Current_Rating: TBD; DNI: DNI; Device_File: 711-60001-01; Manufacturer: Keystone; Manufacturer_PN: 5000; Mated_Height: 4.57mm; Operating_Temp: TBD; Part_Status: In Des; Pins: 1; Row_pitch: NA; Shrouding: NA
U8 = TPS63000_3: Buck-Boost Regulator, 5V, 2A, VFQFN; CLASS: DISCRETE; CY_PN: 470-60004-01; Device File: 470-60004-01; Device_File: 470-60004-01; Manufacturer: Texas Instruments; ROOM: room1; Sub_Asm: Power In
U9 = LDO-1IN_2-4GND_3OUT: IC,Linear Voltage Regulator, IC Positive Fixed, 1 Output, 1A, TO-263; Approved: Approved; CY_PN: 471-60060-01; Device_File: 471-60060-01; Lifecycle: Active; Manufacturer: Texas Instruments; Operating_Temp: -40°C ~ 125°C; Operating_Voltage: 4.5 V  ~  5.5 V; Package: TO-263; Part_Status: Unrel
C5 C12 C13 C17 C47-C49 C55-C57 C60 = CAP-NP: CAP, CER, 1uF, 20%, 10V, X5R, 0402; Approved: Approved; CY_PN: 510-60877-01; Device_File: 510-60877-01; Dielectric: X5R; FPLIST: CAPC1005_0402N,CAPC1005_0402M; Lifecycle: Active; Manufacturer: Wurth; Manufacturer_PN: 885012105012; Operating_Temp: -55°C ~ 85°C; Package: 0402; Part_Status: In Prod; Tolerance: 20%; Voltage: 10V
C2 C9 C18 C27 C30 C46 C50 C58 C61 = CAP-NP: CAP, CER, 0.1uF, 10%, X7R, 16V, 0402; Approved: Approved; CY_PN: 510-60878-01; Device_File: 510-60878-01; Dielectric: X7R; FPLIST: CAPC1005_0402N,CAPC1005_0402M; Lifecycle: Active; Manufacturer: Wurth; Manufacturer_PN: 885012205037; Operating_Temp: -55°C ~ 125°C; Package: 0402; Part_Status: In prod; Tolerance: 10%; Voltage: 16V
C62 = CAP-NP: CAP, CER, 0.1uF, 10%, X7R, 16V, 0402; Approved: Approved; CY_PN: 510-60878-01; DNI: DNI; Device_File: 510-60878-01; Dielectric: X7R; FPLIST: CAPC1005_0402N,CAPC1005_0402M; Lifecycle: Active; Manufacturer: Wurth; Manufacturer_PN: 885012205037; Operating_Temp: -55°C ~ 125°C; Package: 0402; Part_Status: In prod; Tolerance: 10%; Voltage: 16V
J25 = PLG-5-J: CONN, HDR, MALE, SINGLE, 5POS, 2.54mm, TIN, STR, TH; CY_PN: 720-60038-01; DNI: DNI; Device File: 720-60038-01; Manufacturer: Molex; Manufacturer_PN: 22-28-4050
LED3 = DIO-LED: LED, YELLOW, CLEAR, 590nm, 120mcd, 2V, 0805; Approved: Approved; CY_PN: 534-60144-01; Device_File: 534-60144-01; Lifecycle: Active; Manufacturer: Wurth; Manufacturer_PN: 150080YS75000; Operating_Temp: -40°C to 85°C; Package: 0805; Part_Status: Unrel; Voltage: 2V
R61 = RES: RES, FIXED, 49.9K OHM, 1%, 100PPM, 1/10W, 0402; Approved: Approved; CY_PN: 500-61057-01; Device_File: 500-61057-01; FPLIST: RESC1005_0402N,RESC1005_0402M; Lifecycle: Active; Manufacturer: Wurth; Manufacturer_PN: 560112110136; Operating_Temp: -55°C ~ 155°C; Package: 0402; Part_Status: In Prod; Rating: 1/10W; Tolerance: 1%
R62 = RES: RES, FIXED, 49.9K OHM, 1%, 100PPM, 1/10W, 0402; Approved: Approved; CY_PN: 500-61057-01; DNI: DNI; Device_File: 500-61057-01; FPLIST: RESC1005_0402N,RESC1005_0402M; Lifecycle: Active; Manufacturer: Wurth; Manufacturer_PN: 560112110136; Operating_Temp: -55°C ~ 155°C; Package: 0402; Part_Status: In Prod; Rating: 1/10W; Tolerance: 1%
R66 R79 = RES: RES, FIXED, 15K OHM, 1%, 100PPM, 1/10W, 0402; Approved: Approved; CY_PN: 500-61396-01; Device_File: 500-61396-01; FPLIST: RESC1005_0402N,RESC1005_0402M; Lifecycle: Active; Manufacturer: Wurth; Manufacturer_PN: 560112110127; Operating_Temp: -55°C ~ 155°C; Package: 0402; Part_Status: unrel; Rating: 1/10W; Tolerance: 1%
R67 R81 = RES: RES, 30K OHM, 1%, 1/16W, 0402; CY_PN: 500-60558-01; Device File: 500-60558-01; FPLIST: RESC1005_0402N,RESC1005_0402M; Manufacturer: Yageo; Manufacturer_PN: RC0402FR-0730KL; Rating: 1/16W; Tolerance: 1%
R72 R75 = RES: RES, FIXED, 22 OHM, 1%, 100PPM, 1/10W, 0402; Approved: Approved; CY_PN: 500-61390-01; Device_File: 500-61390-01; FPLIST: RESC1005_0402N,RESC1005_0402M; Lifecycle: Active; Manufacturer: Wurth; Manufacturer_PN: 560112110046; Operating_Temp: -55°C ~ 155°C; Package: 0402; Part_Status: unrel; Rating: 1/10W; Tolerance: 1%
R106 = RES: RES, FIXED, 750 OHM, 1%, 1/10W, 0402; Approved: Approved; CY_PN: 500-61409-01; Device_File: 500-61409-01; FPLIST: RESC1005_0402N,RESC1005_0402M; Lifecycle: Active; Manufacturer: Wurth; Manufacturer_PN: 560112110262; Operating_Temp: -55°C ~ 155°C; Package: 0402; Part_Status: unrel; Rating: 1/10W; Tolerance: 1%
R14 R18 R22 R26 R55 R68-R71 R74 R77 R78 R82 R85 R87-R91 R93-R95 R97 R100 R104 R108 R113 R157 R159 = RES: RES, Fixed, 0 OHM, JUMPER, 1/10W, 0603; Approved: Approved; CY_PN: 500-60037-01; Device_File: 500-60037-01; FPLIST: RESC1608_0603N,RESC1608_0603Q,RESC1608_0603M; Lifecycle: Active; Manufacturer: Wurth; Manufacturer_PN: 560112116001; Operating_Temp: -55°C ~ 155°C; Package: 0603; Part_Status: In Prod; Rating: 1/10W; Tolerance: JUMPER
SW3 = SWITCH-PB-12-34: SW, TACT, SPST-NO, 16V, 0.05A, STR, SMD; Actuator_Length: 0.7mm; CY_PN: 770-60033-01; Circuit: SPST-NO; Current_Rating: 0.05A; Device File: 770-60033-01; HARD_LOCATION: YES; Manufacturer: Wurth; Operating_Force: 2.55N; Operating_Temp: -30°C to 85°C; Part_Status: In Prod; Pins: 4; Switch_Function: Off-Mom
U2 = CY8C5868LTI-LP039: IC, CYPRESS, MCU, PSoC 5LP, 32 Bit MCU, 67MHz, 1.8V-5.5V, 68-QFN; Description1: 64KB SRAM, 256KB Flash, 2KB EEPROM, 20-bit Del-Sig, 2x12-bit SAR, 24UDBs, FS USB, CAN, 38 GPIO, 8 SIO; HARD_LOCATION: YES; Lifecycle: Active; Manufacturer: Cypress; Operating_Temp: -40°C to 85°C; Operating_Voltage: 1.8V-5.5V; Package: 68-QFN; Part_Status: In Prod
U5 = SIP32408: IC, LOAD SWITCH, 1CH, 3.5A, 1.1V-5.5V, 0.045OHM, TDFN4; CY_PN: 450-60257-01; Costing: MCU and Power; Description 2: Slew Rate Control, Active High EN, w/o output discharge, Reverse Current Blocking when OFF; Description1: Slew Rate Control, Active High EN, w/o output discharge, Reverse Current Blocking when OFF; Device File: 450-60257-01; Device_File: 450-60257-01; Lifecycle: Active; Manufacturer: VISHAY; Operating_Temp: -40°C to 125°C (Tj); Operating_Voltage: 1.1V-5.5V; Package: TDFN4; Part_Status: In Des
C11 = CAP-NP: CAP, CER, 4.7uF, 10%, X5R, 16V, 0603; CY_PN: 510-60058-01; Device_File: 510-60058-01; Dielectric: X5R; FPLIST: CAPC1608_0603N,CAPC1608_0603M; Lifecycle: Active; Manufacturer: TDK; Manufacturer_PN: C1608X5R1C475K080AC; Operating_Temp: -55°C to 85°C; Package: 0603; Part_Status: In Prod; Tolerance: 10%; Voltage: 16V
C37 = CAP-NP: CAP, CER, 0.22uF, 10%, X7R, 16V, 0402; Approved: Approved; CY_PN: 510-60418-01; Device_File: 510-60418-01; Dielectric: X7R; FPLIST: CAPC1005_0402N,CAPC1005_0402M; Lifecycle: Active; Manufacturer: TDK Corporation; Manufacturer_PN: CGA2B2X7R1C224K050BA; Operating_Temp: -55°C ~ 125°C; Package: 0402; Part_Status: In Prod; Tolerance: 10%; Voltage: 16V
FB1 FB2 = FB: IND, FERRITE BEAD, 1K, 1A, 0.2 OHM, 0603; CY_PN: 520-60177-01; Current: 1A; Device File: 520-60177-01; ESR: 0.2 OHM; Manufacturer: Murata; Manufacturer_PN: BLM18KG102SN1D; Material: Ferrite; Tolerance: 25%
J17 = PLG-2-J: CONN, HDR, MALE, SINGLE, 2POS, 2.54mm, GOLD, STR, TH; Approved: Approved; CY_PN: 720-60349-01; Conatct_Length: 6.0mm; Contact_Finish: GOLD; Current_Rating: 3A; Device_File: 720-60349-01; Lifecycle: Active; Manufacturer: Wurth; Manufacturer_PN: 61300211121; Mated_Height: 8.54mm; Operating_Temp: -40°C to 105°C; Part_Status: In Prod; Pin_Pitch: 2.54mm; Pins: 2; Row_pitch: NA; Rows: 1; Shrouding: Unshrouded
R10 R12 R13 R16 R17 R20 R21 R27 R80 R92 R156 = RES: RES, Fixed, 0 OHM, JUMPER, 1/10W, 0603; Approved: Approved; CY_PN: 500-60037-01; DNI: DNI; Device_File: 500-60037-01; FPLIST: RESC1608_0603N,RESC1608_0603Q,RESC1608_0603M; Lifecycle: Active; Manufacturer: Wurth; Manufacturer_PN: 560112116001; Operating_Temp: -55°C ~ 155°C; Package: 0603; Part_Status: In Prod; Rating: 1/10W; Tolerance: JUMPER
TP1 TP8 TP13 = TP: TESTPOINT, PC, Mini, 0.040"D, Black, TH; CY_PN: 711-60002-01; Device File: 711-60002-01; Manufacturer: Keystone; Manufacturer_PN: 5001
C3 C7 = CAP-NP: CAP, CER, 18pF, 1%, NP0, 50V, 0402; CY_PN: 510-60287-01; Device File: 510-60287-01; Dielectric: NP0; FPLIST: CAPC1005_0402N,CAPC1005_0402M; Manufacturer: Yageo; Manufacturer_PN: CC0402FRNPO9BN180; Part Status: In Prod; Tolerance: 1%; Voltage: 50V
C10 C16 = CAP-NP: CAP, CER, 22pF, 5%, NP0, 50V, 0402; Approved: Approved; CY_PN: 510-60716-01; Device_File: 510-60716-01; Dielectric: NP0; FPLIST: CAPC1005_0402N,CAPC1005_0402M; Lifecycle: Active; Manufacturer: Wurth; Manufacturer_PN: 885012005057; Operating_Temp: -55°C ~ 125°C; Package: 0402; Part_Status: In Prod; Tolerance: 5%; Voltage: 50V
C14 C19 C22 C24 C26 C29 C31-C36 C38 C39 = CAP-NP: CAP, CER, 0.1uF, 10%, X7R, 50V, 0603; Approved: Approved; CY_PN: 510-60730-01; DNI: DNI; Device_File: 510-60730-01; Dielectric: X7R; FPLIST: CAPC1608_0603N,CAPC1608_0603M; Lifecycle: Active; Manufacturer: Wurth; Manufacturer_PN: 885012206095; Operating_Temp: -55°C ~ 125°C; Package: 0603; Part_Status: In Prod; Tolerance: 10%; Voltage: 50V
R24 = RES: RES, 0 OHM, JUMPER, 1A, 0603; CY_PN: 500-60037-01; DNI: DNI; Device File: 500-60037-01; Device_File: 500-60037-01; FPLIST: RESC1608_0603N,RESC1608_0603Q,RESC1608_0603M; Lifecycle: Active; Manufacturer: Yageo; Manufacturer_PN: RC0603JR-070RL; Operating_Temp: -55°C to 155°C; Package: 0603; Part_Status: In Prod; Rating: 1A; SIGNAL_MODEL: RES_RESC1608_0603N_DISCRETE_0_OHM_0_OHM; Tolerance: JUMPER
R41 = RES: RES, Fixed, 10K OHM, 5%, 1/10W, 0603; Approved: Approved; CY_PN: 500-60045-01; DNI: DNI; Device_File: 500-60045-01; FPLIST: RESC1608_0603N,RESC1608_0603Q,RESC1608_0603M; Lifecycle: Active; Manufacturer: Wurth; Manufacturer_PN: 560112116012; Operating_Temp: -55°C ~ 155°C; Package: 0603; Part_Status: In Prod; Rating: 1/10W; Tolerance: 5%
R96 R101 R105 R114 = RES: RES, Fixed, 33 Ohms, 1%, 1/10W, 0603; CY_PN: 500-60540-01; DNI: DNI; Device_File: 500-60540-01; FPLIST: RESC1608_0603N,RESC1608_0603Q,RESC1608_0603M; Lifecycle: Active; Manufacturer: Yageo; Manufacturer_PN: RC0603FR-0733RL; Operating_Temp: -55°C to 155°C; Package: 0603; Part_Status: In Production; Rating: 1/10W; Tolerance: ±1%
U1 = IC_PSC3M5FDS2AFQ1: IC, Infineon, MCU, PSoC C3, M33, 180MHz, 1.7V-3.6V, E-LQFP-80; Approved: Approved; Lifecycle: Active; Manufacturer: Infineon; Operating_Temp: -40°C to 105°C; Operating_Voltage: 1.7V-3.6V; Package: E-LQFP-80; Part_Status: Unrel
Y1 = XTAL-4P-2G4G: CRYSTAL, 16.0000MHZ, 10PF, SMD; CY_PN: 542-60073-01; Frequency_Stability: NA; Manufacturer: Abracon; Manufacturer_PN: ABM10-16.000MHZ-D30-T3; Operating_Temp: -40°C to 85°C; Output_Type: NA; Package: SMD; Part_Status: In Des; Supply_Voltage: NA; Tolerance: 10ppm
Y2 = XTAL-2P: XTAL, 32.768kHz, 20ppm, 12.5pF, SMD; CY_PN: 542-60070-01; Description 2: 1.60mm x 1.00mm x 0.5mm; Device File: 542-60070-01; Manufacturer: TXC; Manufacturer_PN: 9H03277001
ACC6-ACC9 = BUMPON: HW, BUMPON, CYLINDRICAL, BLACK, dia-7.92mm, H-5.46mm; Approved: Approved; CY_PN: 700-60075-01; Lifecycle: Active; Manufacturer: 3M; Part_Status: Unrel
ACC11-ACC13 ACC18 = Jumper_Shunt: HW, JUMPER, CLOSE TYPE, 6mm, 2.54mm Pitch, BLACK; CY_PN: 700-60158-01; Costing: Accessories; Device File: 700-60158-01; Manufacturer: Wurth; Operating_Temp: -40°C to 125°C; Part_Status: Unrel
ACC16 = LABEL: LBL, PCA Label, Vendor Code, Datecode, Serial Number (YYWWVVXXXXX); CY_PN: 899-60120-01; Costing: Accessories; Device File: 899-60120-01; Manufacturer: JETech; Manufacturer_PN: 899-60120-01; Operating_Temp: NA; Part_Status: In Prod
ACC17 = LABEL: LBL, QR CODE, 10mm X 10mm, PSOC CONTROL C3 EVALUATION KIT; CY_PN: 899-60349-01; Costing: Accessories; Device File: 899-60349-01; Manufacturer: JETech; Manufacturer_PN: 899-60349-01

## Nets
GND_EARTH: C79.1 J15.SH1 J15.SH2 J15.SH3 J15.SH4 JMP1.1 JMP1.2 R115.2
GND_SIGNAL: C2.2 C3.2 C4.2 C5.2 C6.2 C7.1 C8.2 C9.2 C10.1 C11.2 C12.2 C13.2 C14.1 C15.2 C16.1 C17.2 C18.2 C19.1 C20.2 C21.2 C22.1 C23.2 C24.1 C26.1 C27.2 C28.2 C29.1 C30.2 C31.1 C32.1 C33.1 C34.1 C35.1 C36.1 C37.2 C38.1 C39.1 C44.2 C45.2 C46.2 C47.2 C48.2 C49.2 C50.2 C51.2 C53.2 C54.2 C55.2 C56.2 C57.2 C58.2 C59.2 C60.2 C61.2 C62.2 C63.2 C65.2 C79.2 C80.2 C81.2 C82.2 C83.2 C84.2 C85.2 C86.2 C87.2 C88.2 C90.2 C92.2 C95.2 C96.2 C97.2 C98.2 D2.A(ANODE) D3.A(ANODE) D6.2 J15.A1(GND_1) J15.A12(GND_2) J15.B1(GND_3) J15.B12(GND_4) J20.2(SHIELD) J20.3(SWITCH) J25.2 LED3.K(CATHODE) Q2.G Q10.S R62.1 R67.1 R80.2 R81.1 R83.2 R98.1 R99.2 R115.1 R117.2 R125.1 R132.2 R134.1 R150.1 R155.1 SW3.3 SW3.4 TP1.1(TP) TP6.1(TP) TP8.1(TP) TP13.1(TP) U1.6(VSS_1) U1.7(VSS_2) U1.77(VSS_3) U1.78(VSS_4) U1.H(VSS_5) U2.5(VSSB) U2.7(VBOOST) U2.8(VBAT) U2.9(VSSD) U2.25(VSSD) U2.43(VSSA) U2.45(VSSD) U2.58(VSSD) U2.62(P2[0]) U2.63(P2[1]) U2.H(EPAD) U5.2(GND) U5.H(PAD) U7.3(GND) U8.4(GND) U8.6(FB2) U8.10(PGND) U8.15(VSEL) U9.2(GND) U9.H(EPAD) Y1.2(GND) Y1.4(GND) ; also on sheet 9 10 11 12 13
VCC_IN: C80.1 C81.1 C82.1 C84.1 D4.K D5.K R121.2 R124.1 TP9.1(TP) U8.12(VIN1) U8.13(VIN2)
VCCD: C11.1 U1.10(VCCD)
VDDA: C30.1 C63.1 FB2.2 R80.1 R93.1 U1.66(VDDA) ; also on sheet 13
VDDD: C18.1 C54.1 FB1.2 U1.9(VDDD) ; also on sheet 12
VDDIO_0: C2.1 C9.1 C44.1 C45.1 C46.1 C51.1 R55.1 U1.20(VDDIO_0_0) U1.40(VDDIO_0_1) U1.49(VDDIO_0_2)
VDDIO_1: C27.1 C59.1 R78.1 U1.80(VDDIO_1)
VIN: C92.1 D5.A D6.1 J20.1(CENTER) R132.1 ; also on sheet 12
AN_A0: C14.2 R68.1 U1.53(AN_A0)
AN_A1: C19.2 R70.1 U1.54(AN_A1)
AN_A2: C22.2 R71.1 U1.55(AN_A2)
AN_A3: C24.2 R74.1 U1.56(AN_A3)
AN_A4: C26.2 R77.1 U1.57(AN_A4)
AN_A5: C29.2 R82.1 U1.58(AN_A5)
AN_A6: C38.2 R85.1 U1.59(AN_A6)
AN_A7: C39.2 R97.1 U1.60(AN_A7)
AN_B2: C31.2 R94.1 U1.63(AN_B2)
AN_B3: C32.2 R91.1 U1.64(AN_B3)
AN_B4: C33.2 R90.1 U1.67(AN_B4)
AN_B5: C34.2 R89.1 U1.68(AN_B5)
AN_B6: C35.2 R88.1 U1.69(AN_B6)
AN_B7: C36.2 R87.1 U1.70(AN_B7)
ARD_A0: R68.2 ; also on sheet 11 12
ARD_A1: R70.2 ; also on sheet 11 12
ARD_A2: R71.2 ; also on sheet 11 12
ARD_A3: R74.2 ; also on sheet 11 12
ARD_A4: R77.2 ; also on sheet 11 12
ARD_A5: R82.2 ; also on sheet 11 12
ARD_A6: R85.2 ; also on sheet 11 12
ARD_A7: R97.2 ; also on sheet 12
ARD_B0: U1.61(AN_B0) ; also on sheet 13
ARD_B1: U1.62(AN_B1) ; also on sheet 13
ARD_B2: R94.2 ; also on sheet 12
ARD_B3: R91.2 ; also on sheet 12
ARD_B5: R89.2 ; also on sheet 12
ARD_B6: R88.2 ; also on sheet 12
ARD_B7: R87.2 ; also on sheet 11 12
CAN_RX1: U1.37(P5.2) ; also on sheet 10
CAN_TX1: U1.38(P5.3) ; also on sheet 10
CS: R20.2 R41.2 R113.2 R114.1 U1.71(P8.0)
DFU_SW1: U1.21(P2.2) ; also on sheet 12
DFU_SW2: U1.22(P2.3) ; also on sheet 12
ECO_IN: R17.1 R18.2 U1.14(P1.0)
ECO_OUT: R13.2 R14.1 U1.15(P1.1)
ETM_TRACE_CLK: R24.1 ; also on sheet 9
ETM_TRACE_D0: R20.1 ; also on sheet 9
ETM_TRACE_D1: R16.1 ; also on sheet 9
ETM_TRACE_D2: R12.1 ; also on sheet 9
ETM_TRACE_D3: R10.1 ; also on sheet 9
EXT_CLK: R27.2 TP4.1(TP)
I2C_SCL: U1.79(P9.0) ; also on sheet 9
I2C_SDA: U1.2(P9.2) ; also on sheet 9
KP_I2C_SCL: U2.38(P12[0]) ; also on sheet 9
KP_I2C_SDA: U2.39(P12[1]) ; also on sheet 9
KP_RESET: U2.3(P12[4]) ; also on sheet 9
KP_SWCLK: U2.47(P12[3]) ; also on sheet 9
KP_SWDIO: U2.46(P12[2]) ; also on sheet 9
KP_USB_DM: J15.A7(DN1) J15.B7(DN2) R72.1 U7.1(IN1)
KP_USB_DP: J15.A6(DP1) J15.B6(DP2) R75.1 U7.2(IN2)
KP_VBUS: D4.A Q3.D R102.2 R108.2 R117.1
KP_VBUS_IN: C65.1 D3.K(CATHODE) J15.A4(VBUS_1) J15.A9(VBUS_2) J15.B4(VBUS_3) J15.B9(VBUS_4) Q2.D R102.1 TP7.1(TP)
LPCOMP0_INN: R95.1 ; also on sheet 12
LPCOMP0_INP: R113.1 ; also on sheet 12
LPCOMP1_INN: R100.1 ; also on sheet 12
LPCOMP1_INP: R104.1 ; also on sheet 12
MISO: R12.2 R104.2 R105.1 U1.73(P8.2)
MOSI: R16.2 R95.2 R96.1 U1.72(P8.1)
P0_1: R21.2 ; also on sheet 12
P1_0: R17.2 ; also on sheet 12
P1_1: R13.1 ; also on sheet 12
P2_0: U1.18(P2.0) ; also on sheet 9
P2_1: U1.19(P2.1) ; also on sheet 9
P3_0: U1.23(P3.0) ; also on sheet 11 12
P3_1: U1.24(P3.1) ; also on sheet 11 12
P3_VDD: FB1.1 FB2.1 J17.1 R55.2 R69.2 R78.2 R157.2
P4_4: U1.31(P4.4) ; also on sheet 9
P4_5: U1.32(P4.5) ; also on sheet 11 12
P5_0: U1.35(P5.0) ; also on sheet 12
P5LP1_2: SW3.1 SW3.2 U2.13(P1[2])
P5LP1_4: R106.2 U2.15(P1[4])
P5LP2_2: U2.64(P2[2])
P5LP2_3: U2.65(P2[3])
P5LP2_4: U2.66(P2[4])
P5LP_SIO_VREF: R61.2 R62.2 U2.48(P0[0])
P5LP_SWCLK: J25.4 U2.12(P1[1])
P5LP_SWDIO: J25.5 U2.11(P1[0])
P5LP_VCCD: C15.1 C17.1 U2.26(VCCD) U2.57(VCCD)
P5LP_VDD: C4.1 C6.1 C8.1 C20.1 C21.1 C23.1 C28.1 C47.1 C48.1 C49.1 C55.1 C56.1 C57.1 C60.1 J25.1 R79.1 R108.1 U2.17(VDDIO1) U2.24(VDDD) U2.35(VDDIO3) U2.44(VDDA) U2.52(VDDIO) U2.59(VDDD) U2.67(VDDIO2)
P5LP_XRES: J25.3 U2.10(~{XRES})
P7_4: R24.2 R159.2 U1.48(P7.4)
P7_6: U1.51(P7.6) ; also on sheet 10 11 12
P7_7: U1.52(P7.7) ; also on sheet 11 12
P8_4: U1.75(P8.4) ; also on sheet 12
P8_5: U1.76(P8.5) ; also on sheet 12
P9_4: U1.4(P9.4) ; also on sheet 11 12
P9_5: U1.5(P9.5) ; also on sheet 11 12
PERI_HRPWM_0: R159.1 ; also on sheet 13
PERI_HRPWM_1: U1.50(P7.5) ; also on sheet 13
PERI_HRPWM_2: U1.33(P4.6) ; also on sheet 12
PERI_HRPWM_3: U1.34(P4.7) ; also on sheet 12
POT: R90.2 ; also on sheet 13
PWM_SHIELD: U1.36(P5.1) ; also on sheet 11 12
SPI_CLK_ARD: U1.44(P7.0) ; also on sheet 11 12
SPI_CLK_FLASH: R101.2 ; also on sheet 10
SPI_CLK_MCU: R10.2 R100.2 R101.1 U1.74(P8.3)
SPI_CS01_ARD: U1.47(P7.3) ; also on sheet 11 12
SPI_CS_FLASH: R114.2 ; also on sheet 10
SPI_MISO_ARD: U1.46(P7.2) ; also on sheet 11 12
SPI_MISO_FLASH: R105.2 ; also on sheet 10
SPI_MOSI_ARD: U1.45(P7.1) ; also on sheet 11 12
SPI_MOSI_FLASH: R96.2 ; also on sheet 10
TCLK_SWCLK_MCU: U1.16(P1.2) ; also on sheet 9
TCPWM1_COMPL_EXP_MCU: U1.28(P4.1) ; also on sheet 9
TCPWM1_EXP_MCU: U1.27(P4.0) ; also on sheet 9
TCPWM2_COMPL_EXP_MCU: U1.3(P9.3) ; also on sheet 12
TCPWM2_EXP_MCU: U1.1(P9.1) ; also on sheet 12
TCPWM_COMPL_EXP_MCU: U1.30(P4.3) ; also on sheet 9
TCPWM_EXP_MCU: U1.29(P4.2) ; also on sheet 9
TMS_SWDIO_MCU: U1.17(P1.3) ; also on sheet 9
UART_1_RX: U2.21(P12[7]) ; also on sheet 9
UART_1_TX: U2.20(P12[6]) ; also on sheet 9
UART_CTS_1: U1.39(P6.0) ; also on sheet 11 12
UART_RTS_1: U1.41(P6.1) ; also on sheet 11 12
UART_RX: U1.42(P6.2) ; also on sheet 9
UART_RX_0_MIK: U1.25(P3.2) ; also on sheet 11 12
UART_TX: U1.43(P6.3) ; also on sheet 9
UART_TX_0_MIK: U1.26(P3.3) ; also on sheet 11 12
USB_V_SENSE: R79.2 R81.2 U2.19(P1[7])
VAREF_EXT: C37.1 R92.2 R93.2 U1.65(VAREF_EXT)
VBACKUP: C50.1 C53.1 R69.1 U1.11(VBACKUP)
VOUT_3V3: C61.1 C97.1 C98.1 J17.2 R116.1 R156.2 TP10.1(TP) U5.1(IN) U9.3(OUT) ; also on sheet 11
VOUT_5V0: C83.1 C85.1 C86.1 C87.1 C88.1 C91.1 C95.1 C96.1 R123.1 R126.1 TP12.1(TP) U8.7(VOUT1) U8.8(VOUT2) U9.1(IN) ; also on sheet 10 11
VREFH: R92.1 ; also on sheet 11 12
VTARG_MEAS: R66.2 R67.2 U2.32(P3[3])
VTARG_REF: C58.1 Q10.G R41.1 R61.1 R66.1 R150.2 U5.4(OUT) ; also on sheet 9 10 11 12
VTARG_REF_EN: R86.2 R156.1 R157.1
WCO_IN: R21.1 R22.1 U1.13(P0.1)
WCO_OUT: R26.1 R27.1 U1.12(P0.0)
XRES_L_MCU: U1.8(XRES) ; also on sheet 9 11 12
N22087450: C12.1 U2.53(P0[4])
N22087778: C5.1 U2.42(VCCA)
N22087991: R75.2 U2.22(P15[6]_D+)
N22087993: R72.2 U2.23(P15[7]_D-)
N22088003: C13.1 U2.31(P3[2])
N22088231: LED3.A(ANODE) R106.1
N22129895: C10.2 R22.2 Y2.2
N22129929: C7.2 R18.1 Y1.3
N22129931: C3.1 R14.2 Y1.1
N22129945: C16.2 R26.2 Y2.1
N22154314: J15.A5(CC1) R99.1
N22154327: J15.B5(CC2) R83.1
N22156925: L1.1 U8.11(L1)
N22156929: L1.2 U8.9(L2)
N22157101: R121.1 U8.14(EN)
N22157103: R126.2 TP11.1(TP) U8.2(PG)
N22157131: R124.2 R125.2 U8.1(PS/SYNC)
N22157141: C90.1 U8.3(VAUX)
N22157156: C91.2 R123.2 R134.2 U8.5(FB)
N22191822: C62.1 R86.1 R155.2 U5.3(EN)
N22258799: Q1.S Q2.S Q3.S R84.2
N22258824: Q1.D Q3.G R98.2
N22258828: D2.K(CATHODE) Q1.G R84.1
N22307724: LED4.K(CATHODE) Q10.D
N22500842: LED4.A(ANODE) R116.2

Not connected (* = marked no-connect by the designer): J15 A8(SBU1) B8(SBU2); U2 1(P2[6])* 2(P2[7])* 4(P12[5])* 6(IND)* 14(P1[3])* 16(P1[5])* 18(P1[6])* 27(P15[0])* 28(P15[1])* 29(P3[0])* 30(P3[1])* 33(P3[4])* 34(P3[5])* 36(P3[6])* 37(P3[7])* 40(P15[2])* 41(P15[3])* 49(P0[1])* 50(P0[2])* 51(P0[3])* 54(P0[5])* 55(P0[6])* 56(P0[7])* 60(P15[4])* 61(P15[5])* 68(P2[5])*

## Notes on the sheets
sheet 1
- Accessories
- Cylindrical Bump-ons
- Jumper Shunts
- PCBA Labels
sheet 2
- KIT_PSC3M5_EVK
- CONTENTS
- PAGE
- DESCRIPTION
- 01
- Title, Table of Contents & Drawing Numbers
- 02
- Functional Block Diagram
- 03
- Power Supply - 1
- 04
- Power Supply - 2
- 05
- KitProg3 Interface
- 06
- PSoC C3 MCU power
- 07
- PSoC C3 MCU signal
- 08
- Communication and Program
- 09
- CAN Interface
- 10
- Interface Headers
- 11
- Expansion headers and buttons
- 12
- HRPWM Output and  POT
- 13
- Accesories
- 14
- Revision history
- Drawing Numbers
- PCBA
- PCB
- FAB DRW
- ASSY DRW
- SCH DRW
sheet 4
- USB Power Supply and Interface
- 20V Protection Circuit
- Power Supply 'OR'ing
- Power LED
- DC Power Jack
- 12V, 2A
- Note: Recommonded input supply 7V-12V
sheet 5
- 5V Buck-Boost Regulator
- 3.3V LDO max 1A
sheet 6
- PSoC™ 5LP based KitProg3
- Decoupling Capacitors
- PSoC™ 5LP Power
- SAR Bypass
  Capacitor
- Voltage Monitoring
- VTARG REF. Voltage
- Note: Switch is used to reduce the
  leakage on P3_VDD domain.
- Del-Sig Bypass Capacitor
- Optional Programming Header
- KitProg3 H/W Revision
- Mode Switch
- KitProg3 Status LED
- Bit 0
- Bit 1
- Bit 2
- Bit 3
- Bit 4
- ID = 0x03
sheet 7
- Decoupling capacitors
- Current Measurement Jumper
- PSOC C3 Device Power
- PSOC C3 Device Power
- Note: VAREF_EXT Voltage ranged is 1.7V-3.6V
sheet 8
- PSOC C3 I/Os
- ECO
- WCO
- Note: Tripad
- Note: Tripad
- Antialiasing filter provision for ADC input
- Note: QUADpad
- Note: Tripad
